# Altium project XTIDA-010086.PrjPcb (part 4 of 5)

## Sheet XTIDA-010086_Bias Power Supply.SchDoc: Control card
size 431 x 279 mm; Date: Not shown in title block; ApprovedBy: Not shown in title block; CheckedBy: Not shown in title block; Author: Not shown in title block; CompanyName: Not shown in title block; DrawnBy: Jeff Xie; Engineer: Not shown in title block; Organization: Not shown in title block; Address1: Not shown in title block; Address2: Not shown in title block; Address3: Not shown in title block; Address4: Not shown in title block; DocumentNumber: 2; Revision: Use project parameter SCH_Rev; SheetNumber: 7; SheetTotal: 8; PageSetup: Record=PageOptions¦CenterHorizontal=True¦CenterVertical=True¦PrintScale=1.00¦XCorrection=1.00¦YCorrection=1.00¦PrintKind=0¦BorderSize=5000000¦LeftOffset=0¦BottomOffset=0¦Orientation=2¦PaperLength=1000¦PaperWidth=1000¦Scale=100¦PaperSource=15¦PrintQuality=600¦MediaType=1¦DitherType=10¦PaperKind=Letter¦PrintScaleMode=1
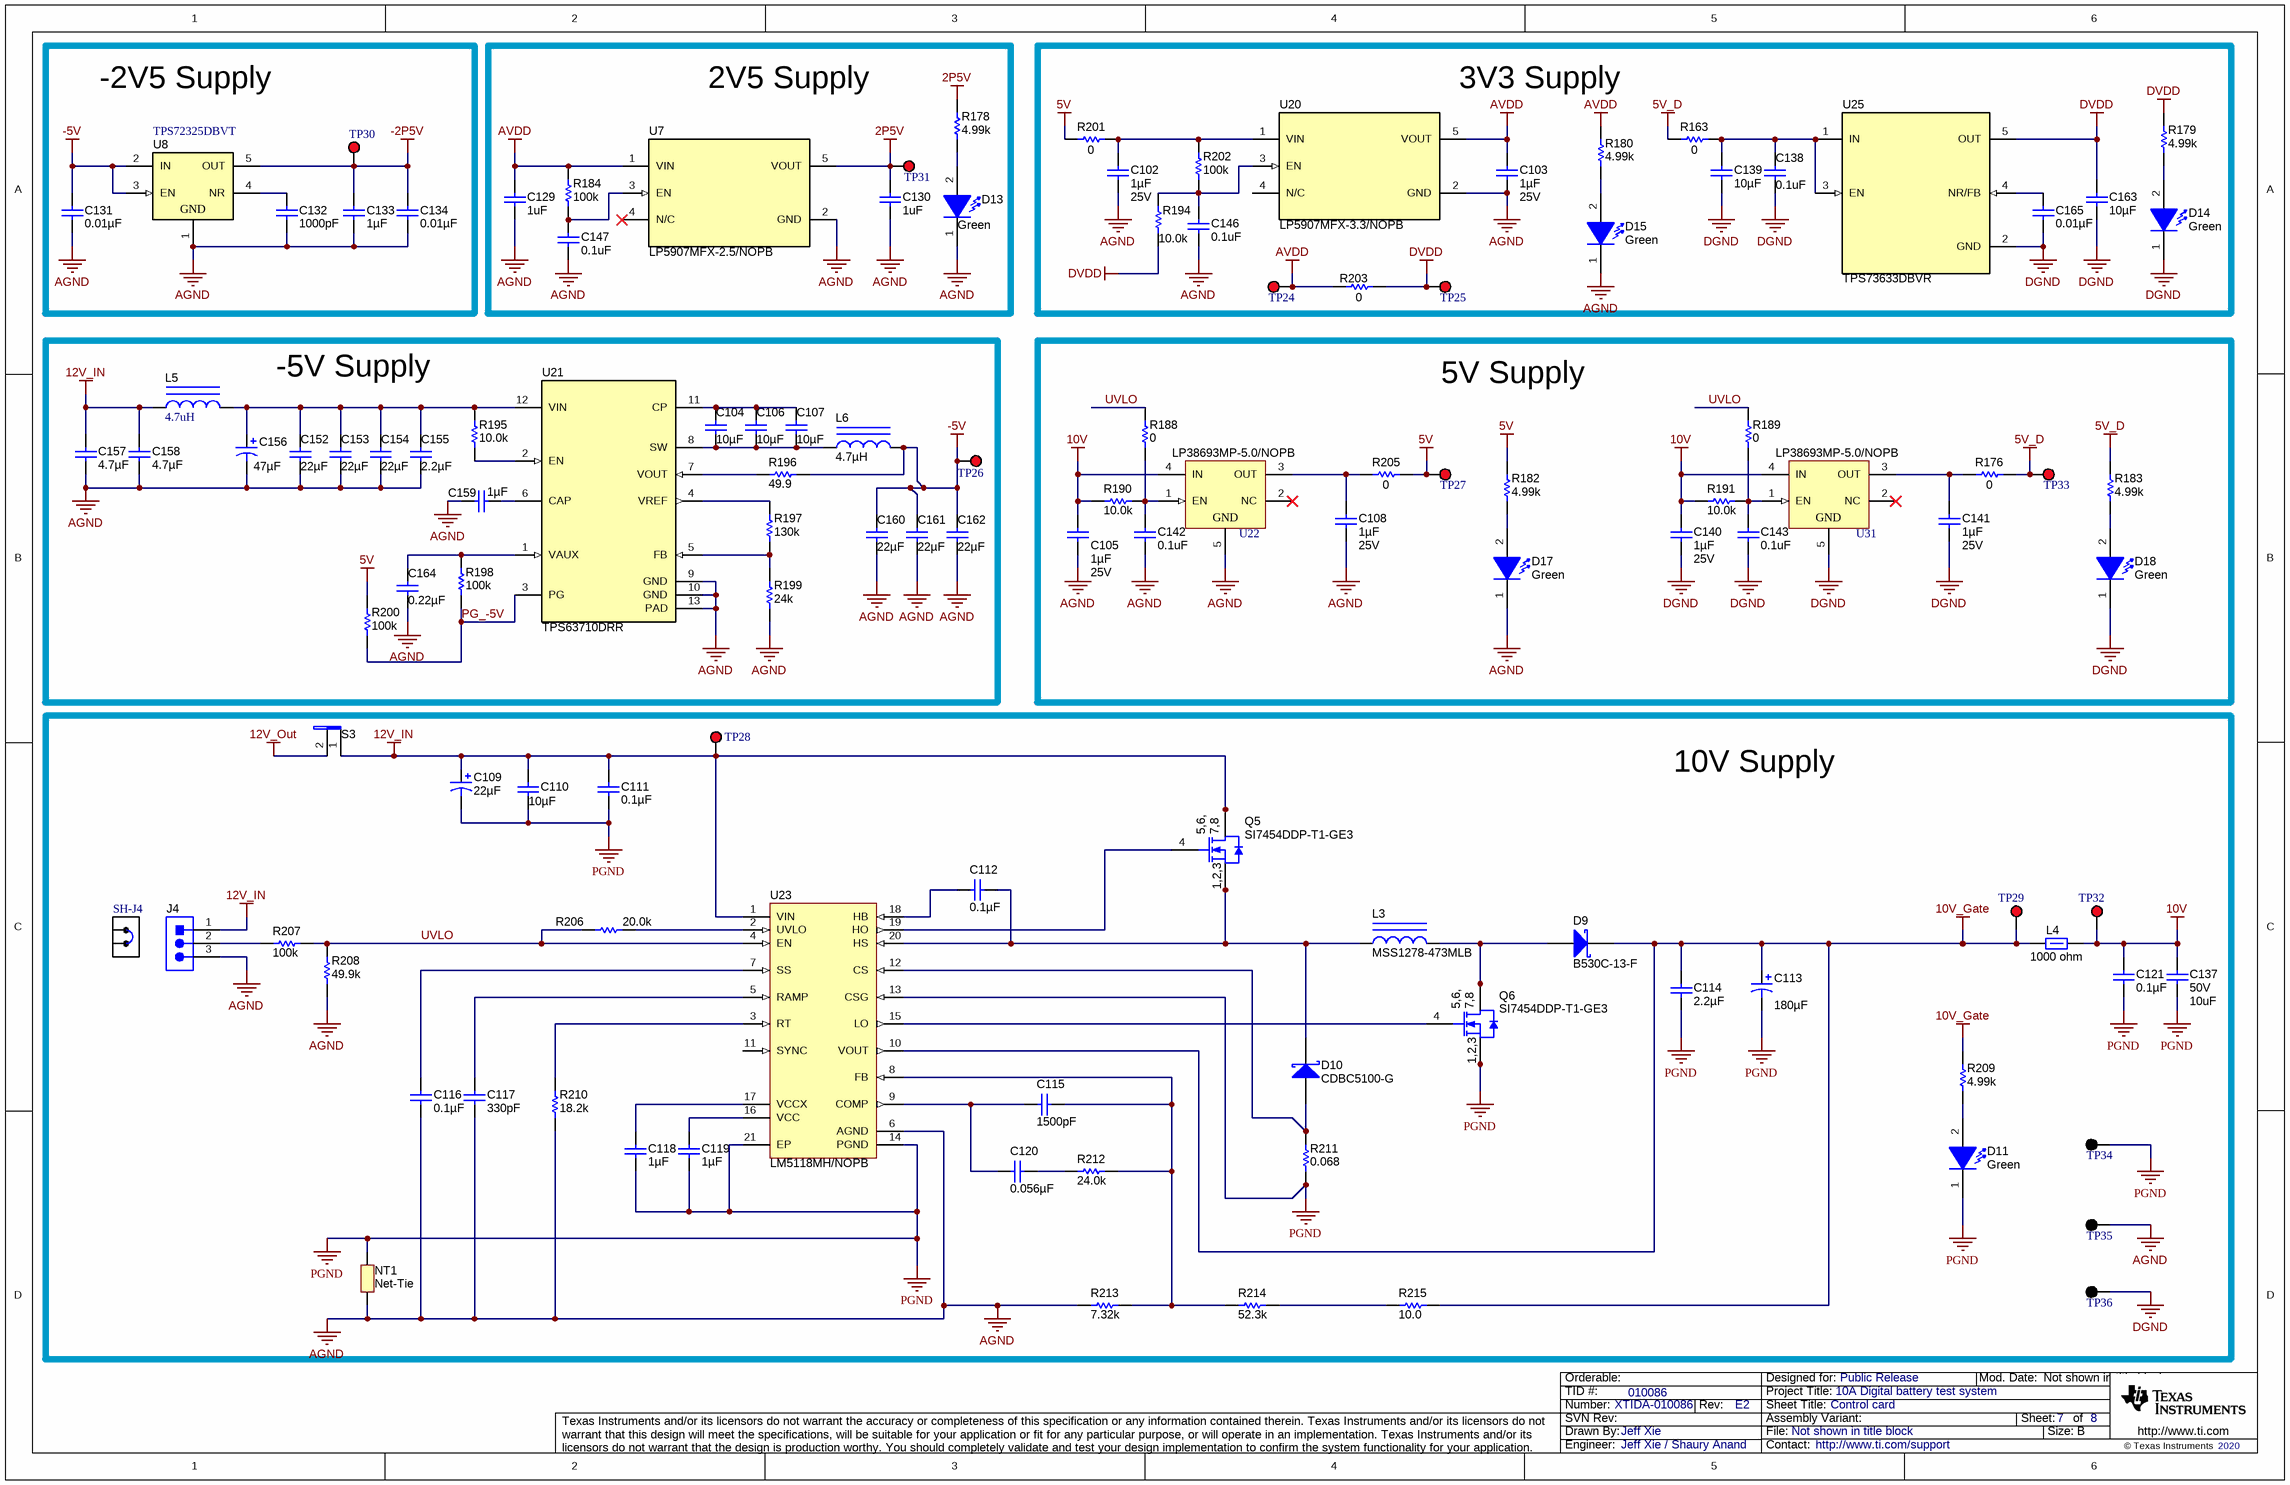
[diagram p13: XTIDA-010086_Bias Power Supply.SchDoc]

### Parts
C102  Cap_F: 1µF  VDC_V: 25V  [0603]  (hidden comment: C0603C105K3RACTU)
C103  Cap_F: 1µF  VDC_V: 25V  [0603]  (hidden comment: C0603C105K3RACTU)
C104  ValueDisplayed: 10µF  [0805_HV1]  (hidden comment: EMK212BB7106MG-T)
C105  Cap_F: 1µF  VDC_V: 25V  [0603]  (hidden comment: C0603C105K3RACTU)
C106  ValueDisplayed: 10µF  [0805_HV1]  (hidden comment: EMK212BB7106MG-T)
C107  ValueDisplayed: 10µF  [0805_HV1]  (hidden comment: EMK212BB7106MG-T)
C108  Cap_F: 1µF  VDC_V: 25V  [0603]  (hidden comment: C0603C105K3RACTU)
C109  ValueDisplayed: 22µF  [CAPSMT_62_JA0]  (hidden comment: EMVH101ADA220MJA0G)
C110  ValueDisplayed: 10µF  [2220_250]  (hidden comment: C5750X7S2A106M230KB)
C111  ValueDisplayed: 0.1µF  [0805_HV]  (hidden comment: C2012X7R2A104K125AA)
C112  ValueDisplayed: 0.1µF  [0603L]  (hidden comment: GRM188R72A104KA35D)
C113  ValueDisplayed: 180µF  [CAPSMT_62_HC0]  (hidden comment: APXA160ARA181MHC0G)
C114  ValueDisplayed: 2.2µF  [0805_HV]  (hidden comment: C2012X7R1C225K125AB)
C115  ValueDisplayed: 1500pF  [0603L]  (hidden comment: GRM1885C2A152JA01D)
C116  ValueDisplayed: 0.1µF  [0603L]  (hidden comment: GRM188R72A104KA35D)
C117  ValueDisplayed: 330pF  [0603L]  (hidden comment: C1608C0G2A331J080AA)
C118  ValueDisplayed: 1µF  [0603L]  (hidden comment: GRM188R71E105KA12D)
C119  ValueDisplayed: 1µF  [0603L]  (hidden comment: GRM188R71E105KA12D)
C120  ValueDisplayed: 0.056µF  [0603L]  (hidden comment: GRM188R71H563KA93D)
C121  ValueDisplayed: 0.1µF  [0805_HV]  (hidden comment: C2012X7R2A104K125AA)
C129  ValueDisplayed: 1uF  [0805_HV]  (hidden comment: Capacitor)
C130  ValueDisplayed: 1uF  [0805_HV]  (hidden comment: Capacitor)
C131  ValueDisplayed: 0.01µF  [0603]  (hidden comment: 06031C103KAT2A)
C132  ValueDisplayed: 1000pF  [0603]  (hidden comment: 06031C102JAT2A)
C133  ValueDisplayed: 1µF  [0603]  (hidden comment: GRM188R71E105KA12D)
C134  ValueDisplayed: 0.01µF  [0603]  (hidden comment: 06031C103KAT2A)
C137  VDC_V: 50V  ValueDisplayed: 10uF  [1210_280]  (hidden comment: C3225X7R1H106M250AC)
C138  ValueDisplayed: 0.1uF  [0603]  (hidden comment: Capacitor)
C139  ValueDisplayed: 10µF  [0603]  (hidden comment: GRM188R61E106MA73D)
C140  Cap_F: 1µF  VDC_V: 25V  [0603]  (hidden comment: C0603C105K3RACTU)
C141  Cap_F: 1µF  VDC_V: 25V  [0603]  (hidden comment: C0603C105K3RACTU)
C142  ValueDisplayed: 0.1uF  [0603]  (hidden comment: Capacitor)
C143  ValueDisplayed: 0.1uF  [0603]  (hidden comment: Capacitor)
C146  ValueDisplayed: 0.1uF  [0603]  (hidden comment: Capacitor)
C147  ValueDisplayed: 0.1uF  [0603]  (hidden comment: Capacitor)
C152  ValueDisplayed: 22µF  [1206_190]  (hidden comment: EMK316BB7226ML-T)
C153  ValueDisplayed: 22µF  [1206_190]  (hidden comment: EMK316BB7226ML-T)
C154  ValueDisplayed: 22µF  [1206_190]  (hidden comment: EMK316BB7226ML-T)
C155  ValueDisplayed: 2.2µF  [0603_HV]  (hidden comment: EMK107BB7225KA-T)
C156  ValueDisplayed: 47µF  [F95_B]  (hidden comment: F951C476MBAAQ2)
C157  ValueDisplayed: 4.7µF  [1206]  (hidden comment: GRM319R61E475KA12D)
C158  ValueDisplayed: 4.7µF  [1206]  (hidden comment: GRM319R61E475KA12D)
C159  ValueDisplayed: 1µF  [0402]  (hidden comment: C1005X5R1C105K050BC)
C160  ValueDisplayed: 22µF  [0805_HV1]  (hidden comment: C2012X7S1A226M125AC)
C161  ValueDisplayed: 22µF  [0805_HV1]  (hidden comment: C2012X7S1A226M125AC)
C162  ValueDisplayed: 22µF  [0805_HV1]  (hidden comment: C2012X7S1A226M125AC)
C163  ValueDisplayed: 10µF  [0603]  (hidden comment: GRM188R61E106MA73D)
C164  ValueDisplayed: 0.22µF  [0402]  (hidden comment: GRM155R71C224KA12D)
C165  ValueDisplayed: 0.01µF  [0603]  (hidden comment: 06031C103KAT2A)
D9  B530C-13-F  [SMC]
D10  CDBC5100-G  [SMC]
D11  value Green  [WL-SMCW_GREEN]  (hidden comment: 150060VS75000)
D13  value Green  [WL-SMCW_GREEN]  (hidden comment: 150060VS75000)
D14  value Green  [WL-SMCW_GREEN]  (hidden comment: 150060VS75000)
D15  value Green  [WL-SMCW_GREEN]  (hidden comment: 150060VS75000)
D17  value Green  [WL-SMCW_GREEN]  (hidden comment: 150060VS75000)
D18  value Green  [WL-SMCW_GREEN]  (hidden comment: 150060VS75000)
J4  0022284033  [Molex_0022284033]  (value not drawn)
L3  MSS1278-473MLB  [mss1278]
L4  value 1000 ohm  [1806_HighSpeed]  (hidden comment: BLM41PG102SN1L)
L5  ValueDisplayed: 4.7uH  [MAKK2016]  (hidden comment: MAKK2016T4R7M)
L6  ValueDisplayed: 4.7µH  [XFL4020]  (hidden comment: XFL4020-472MEB)
NT1  Net-Tie  [Net-Tie_10mil]  (net tie, no BOM)
Q5  SI7454DDP-T1-GE3  [PowerPAK_SO-8]
Q6  SI7454DDP-T1-GE3  [PowerPAK_SO-8]
R163  ValueDisplayed: 0  [0603]  (hidden comment: Resistor)
R176  ValueDisplayed: 0  [0603]  (hidden comment: Resistor)
R178  ValueDisplayed: 4.99k  [0603L]  (hidden comment: CRCW06034K99FKEA)
R179  ValueDisplayed: 4.99k  [0603L]  (hidden comment: CRCW06034K99FKEA)
R180  ValueDisplayed: 4.99k  [0603L]  (hidden comment: CRCW06034K99FKEA)
R182  ValueDisplayed: 4.99k  [0603L]  (hidden comment: CRCW06034K99FKEA)
R183  ValueDisplayed: 4.99k  [0603L]  (hidden comment: CRCW06034K99FKEA)
R184  ValueDisplayed: 100k  [0603]  (hidden comment: CRCW0603100KFKEA)
R188  ValueDisplayed: 0  [0402]  (hidden comment: CRCW04020000Z0ED)
R189  ValueDisplayed: 0  [0402]  (hidden comment: CRCW04020000Z0ED)
R190  ValueDisplayed: 10.0k  [0603]  (hidden comment: RC0603FR-0710KL)
R191  ValueDisplayed: 10.0k  [0603]  (hidden comment: RC0603FR-0710KL)
R194  ValueDisplayed: 10.0k  [0603]  (hidden comment: RC0603FR-0710KL)
R195  ValueDisplayed: 10.0k  [0603]  (hidden comment: RC0603FR-0710KL)
R196  ValueDisplayed: 49.9  [0402]  (hidden comment: CRCW040249R9FKED)
R197  ValueDisplayed: 130k  [0402]  (hidden comment: CRCW0402130KFKED)
R198  ValueDisplayed: 100k  [0402]  (hidden comment: CRCW0402100KDHEDP)
R199  ValueDisplayed: 24k  [0402]  (hidden comment: CRCW040224K0JNED)
R200  ValueDisplayed: 100k  [0402]  (hidden comment: CRCW0402100KDHEDP)
R201  ValueDisplayed: 0  [0603]  (hidden comment: Resistor)
R202  ValueDisplayed: 100k  [0603]  (hidden comment: CRCW0603100KFKEA)
R203  ValueDisplayed: 0  [0603]  (hidden comment: Resistor)
R205  ValueDisplayed: 0  [0603]  (hidden comment: Resistor)
R206  ValueDisplayed: 20.0k  [0603L]  (hidden comment: CRCW060320K0FKEA)
R207  ValueDisplayed: 100k  [0603]  (hidden comment: RC0603FR-07100KL)
R208  ValueDisplayed: 49.9k  [0603]  (hidden comment: CRCW060349K9FKEA)
R209  ValueDisplayed: 4.99k  [0603L]  (hidden comment: CRCW06034K99FKEA)
R210  ValueDisplayed: 18.2k  [0603L]  (hidden comment: CRCW060318K2FKEA)
R211  ValueDisplayed: 0.068  [0612]  (hidden comment: PRL1632-R068-F-T1)
R212  ValueDisplayed: 24.0k  [0603L]  (hidden comment: RC0603FR-0724KL)
R213  ValueDisplayed: 7.32k  [0603]  (hidden comment: RC0603FR-077K32L)
R214  ValueDisplayed: 52.3k  [0603]  (hidden comment: RC0603FR-0752K3L)
R215  ValueDisplayed: 10.0  [0603L]  (hidden comment: CRCW060310R0FKEA)
S3  L101011MS02Q  [SW_ L101011MS02Q]  (value not drawn)
SH-J4  60900213421  [Wurth_60900213421]  (value not drawn)
TP24  5000  [Keystone5000]  (value not drawn)
TP25  5000  [Keystone5000]  (value not drawn)
TP26  5000  [Keystone5000]  (value not drawn)
TP27  5000  [Keystone5000]  (value not drawn)
TP28  5000  [Keystone5000]  (value not drawn)
TP29  5000  [Keystone5000]  (value not drawn)
TP30  5000  [Keystone5000]  (value not drawn)
TP31  5000  [Keystone5000]  (value not drawn)
TP32  5000  [Keystone5000]  (value not drawn)
TP33  5000  [Keystone5000]  (value not drawn)
TP34  5001  [Keystone5001]  (value not drawn)
TP35  5001  [Keystone5001]  (value not drawn)
TP36  5001  [Keystone5001]  (value not drawn)
U7  LP5907MFX-2.5/NOPB  [DBV0005A_L]
U8  TPS72325DBVT  [DBV0005A_N]
U20  LP5907MFX-3.3/NOPB  [DBV0005A_N]
U21  TPS63710DRR  [DRR0012C]
U22  LP38693MP-5.0/NOPB  [NDC0005A_N]
U23  LM5118MH/NOPB  [MXA20A_N]
U25  TPS73633DBVR  [DBV0005A_N]
U31  LP38693MP-5.0/NOPB  [NDC0005A_N]

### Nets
2P5V: C130.1 R178.1 TP31.1 U7.5(VOUT)
5V: R182.1 R200.2 R201.1 R205.2 TP27.1
5V_D: R163.1 R176.2 R183.1 TP33.1
10V: C105.1 C121.1 C137.1 C140.1 L4.2 R190.2 R191.2 TP32.1 U22.4(IN) U31.4(IN)
10V_Gate: C113.1(+) C114.1 D9.1(K) L4.1 R209.1 R215.2 TP29.1 U23.10(VOUT)
12V_IN: C109.1(+) C110.1 C111.1 C157.1 C158.1 J4.1 L5.1 Q5.5(D) Q5.6(D) Q5.7(D) Q5.8(D) Q5.9(D) S3.1 TP28.1 U23.1(VIN)
12V_Out: S3.2
-2P5V: C133.1 C134.1 TP30.1 U8.5(OUT)
-5V: C131.1 C160.1 C161.1 C162.1 L6.2 R196.1 TP26.1 U8.2(IN) U8.3(EN)
AGND: C102.2 C103.2 C105.2 C108.2 C116.2 C117.2 C129.2 C130.2 C131.2 C132.2 C133.2 C134.2 C142.2 C146.2 C147.2 C152.2 C153.2 C154.2 C155.2 C156.2(-) C157.2 C158.2 C159.1 C160.2 C161.2 C162.2 C164.2 D13.1(K) D15.1(K) D17.1(K) J4.3 NT1.1 R199.1 R208.1 R210.1 R213.1 TP35.1 U7.2(GND) U8.1(GND) U20.2(GND) U21.9(GND) U21.10(GND) U21.13(PAD) U22.5(GND) U23.6(AGND)
AVDD: C103.1 C129.1 R180.1 R184.2 R203.1 TP24.1 U7.1(VIN) U20.5(VOUT)
DGND: C138.2 C139.2 C140.2 C141.2 C143.2 C163.2 C165.2 D14.1(K) D18.1(K) TP36.1 U25.2(GND) U31.5(GND)
DVDD: C163.1 R179.1 R194.1 R203.2 TP25.1 U25.5(OUT)
PGND: C109.2(-) C110.2 C111.2 C113.2(-) C114.2 C118.2 C119.2 C121.2 C137.2 D11.1(K) NT1.2 Q6.1(S) Q6.2(S) Q6.3(S) R211.1 TP34.1 U23.13(CSG) U23.14(PGND) U23.21(EP)
PG_-5V: R198.1 R200.1 U21.3(PG)
UVLO: R188.1 R189.1 R206.1 R207.1 R208.2 U23.4(EN)
NetC102_1: C102.1 R201.2 R202.2 U20.1(VIN)
NetC104_1: C104.1 C106.1 C107.1 U21.11(CP)
NetC104_2: C104.2 C106.2 C107.2 L6.1 U21.8(SW)
NetC108_1: C108.1 R205.1 U22.3(OUT)
NetC112_1: C112.1 D10.1(K) L3.1 Q5.1(S) Q5.2(S) Q5.3(S) U23.20(HS)
NetC112_2: C112.2 U23.18(HB)
NetC115_1: C115.1 C120.1 U23.9(COMP)
NetC115_2: C115.2 R212.1 R213.2 R214.1 U23.8(FB)
NetC116_1: C116.1 U23.7(SS)
NetC117_1: C117.1 U23.5(RAMP)
NetC118_1: C118.1 U23.17(VCCX)
NetC119_1: C119.1 U23.16(VCC)
NetC120_2: C120.2 R212.2
NetC132_1: C132.1 U8.4(NR)
NetC138_1: C138.1 C139.1 R163.2 U25.1(IN) U25.3(EN)
NetC141_1: C141.1 R176.1 U31.3(OUT)
NetC142_1: C142.1 R188.2 R190.1 U22.1(EN)
NetC143_1: C143.1 R189.2 R191.1 U31.1(EN)
NetC146_1: C146.1 R194.2 R202.1 U20.3(EN)
NetC147_1: C147.1 R184.1 U7.3(EN)
NetC152_1: C152.1 C153.1 C154.1 C155.1 C156.1(+) L5.2 R195.1 U21.12(VIN)
NetC159_2: C159.2 U21.6(CAP)
NetC164_1: C164.1 R198.2 U21.1(VAUX)
NetC165_1: C165.1 U25.4(NR/FB)
NetD9_2: D9.2(A) L3.2 Q6.5(D) Q6.6(D) Q6.7(D) Q6.8(D) Q6.9(D)
NetD10_2: D10.2(A) R211.2 U23.12(CS)
NetD11_2: D11.2(A) R209.2
NetD13_2: D13.2(A) R178.2
NetD14_2: D14.2(A) R179.2
NetD15_2: D15.2(A) R180.2
NetD17_2: D17.2(A) R182.2
NetD18_2: D18.2(A) R183.2
NetJ4_2: J4.2 R207.2
NetQ5_4: Q5.4(G) U23.19(HO)
NetQ6_4: Q6.4(G) U23.15(LO)
NetR195_2: R195.2 U21.2(EN)
NetR196_2: R196.2 U21.7(VOUT)
NetR197_1: R197.1 R199.2 U21.5(FB)
NetR197_2: R197.2 U21.4(VREF)
NetR206_2: R206.2 U23.2(UVLO)
NetR210_2: R210.2 U23.3(RT)
NetR214_2: R214.2 R215.1

Not connected (* = marked no-connect by the designer): U7 4(N/C)*; U20 4(N/C); U22 2(NC)*; U23 11(SYNC); U31 2(NC)*

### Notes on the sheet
- -2V5 Supply
- 2V5 Supply
- 3V3 Supply
- -5V Supply
- (near R189) 5V Supply
- 10V Supply

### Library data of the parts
C102 C103 C105 C108 C140 C141 = CMP-0006867-1: CAP, CERM, 1 uF, 25 V, +/- 10%, X7R, 0603; Manufacturer: Kemet; TaMin_C: -55°C; Polarized: N; SizeAreaWB_mm2: 4.68; Value1: Unknown; U/M: EA; Value: 1uF; TaMax_C: 125°C; SizeZ_mm: 1; SizeX_mm: 1.6; SizeY_mm: 0.8; SizeArea_mm2: 1.28; AEC Category: Q200
C104 C106 C107 = EMK212BB7106MG-T: CAP, CERM, 10 µF, 16 V, +/- 20%, X7R, 0805; Manufacturer: Taiyo Yuden; Polarized: N; CompType: Capacitor; Value: 10uF; U/M: EA; Cap_F: 0.00001; Tolerance_%: 20; Value1: Unknown; VDC_V: 16; Value2: 16V; TaMin_C: -55; TaMax_C: 125; Cap_Case: 0805; AEC Category: Q200
C109 = EMVH101ADA220MJA0G: CAP, AL, 22 µF, 100 V, +/- 20%, 0.55 ohm, SMD; Manufacturer: Chemi-Con; Polarized: Y; CompType: Capacitor; Value: 22uF; U/M: EA; Cap_F: 0.000022; Tolerance_%: 20; VDC_V: 100; Value2: 100V; ESR_ohm: 0.55; IRMS_A: 0.115; TaMin_C: -40; TaMax_C: 125; Cap_Case: JA0
C110 = C5750X7S2A106M230KB: CAP, CERM, 10 µF, 100 V, +/- 20%, X7S,; Manufacturer: TDK; Polarized: N; CompType: Capacitor; Value: 10uF; U/M: EA; Cap_F: 0.00001; Tolerance_%: 20; ESR_ohm: 0.005; Value1: 0.005 ohm; VDC_V: 100; Value2: 100V; IRMS_A: 6.45; TaMin_C: -55; TaMax_C: 125; Cap_Case: 2220; SizeArea_mm2: 28.5; SizeAreaWB_mm2: 53.9; SizeX_mm: 5.7; SizeY_mm: 5; SizeZ_mm: 2.5; AEC Category: Q200
C111 = C2012X7R2A104K125AA: CAP, CERM, 0.1 µF, 100 V, +/- 10%, X7R, 0805; Manufacturer: TDK; Polarized: N; CompType: Capacitor; Value: 0.1uF; U/M: EA; Cap_F: 0.0000001; Tolerance_%: 10; ESR_ohm: 0.0158; Value1: 0.0158 ohm; VDC_V: 100; Value2: 100V; TaMin_C: -55; TaMax_C: 125; Cap_Case: 0805; AEC Category: Q200
C112 C116 = GRM188R72A104KA35D: CAP, CERM, 0.1 µF, 100 V, +/- 10%, X7R, 0603; Manufacturer: MuRata; Polarized: N; CompType: Capacitor; Value: 0.1uF; U/M: EA; Cap_F: 0.0000001; Tolerance_%: 10; Value1: Unknown; VDC_V: 100; Value2: 100V; TaMin_C: -55; TaMax_C: 125; Cap_Case: 0603; AEC Category: Q200
C113 = APXA160ARA181MHC0G: CAP, Aluminum Polymer, 180 µF, 16 V, +/- 20%, 0.016 ohm, HC0 SMD; Manufacturer: Chemi-Con; Polarized: Y; CompType: Capacitor; Value: 180uF; U/M: EA; Cap_F: 0.00018; Tolerance_%: 20; VDC_V: 16; Value2: 16V; ESR_ohm: 0.016; IRMS_A: 4.36; TaMin_C: -55; TaMax_C: 105; SizeAreaWB_mm2: 110.25; SizeArea_mm2: 72.25; SizeX_mm: 8.5; SizeZ_mm: 12.3; AEC Category: Q200; AEC Qualified: N
C114 = C2012X7R1C225K125AB: CAP, CERM, 2.2 µF, 16 V, +/- 10%, X7R, 0805; Manufacturer: TDK; Polarized: N; CompType: Capacitor; Value: 2.2uF; U/M: EA; Cap_F: 0.0000022; Tolerance_%: 10; ESR_ohm: 0.0049; Value1: 0.0049 ohm; VDC_V: 16; Value2: 16V; TaMin_C: -55; TaMax_C: 125; Cap_Case: 0805; AEC Category: Q200
C115 = GRM1885C2A152JA01D: CAP, CERM, 1500 pF, 100 V, +/- 5%, C0G/NP0, 0603; Manufacturer: MuRata; Polarized: N; CompType: Capacitor; Value: 1500pF; U/M: EA; Cap_F: 0.0000000015; Tolerance_%: 5; Value1: Unknown; VDC_V: 100; Value2: 100V; TaMin_C: -55; TaMax_C: 125; Cap_Case: 0603
C117 = C1608C0G2A331J080AA: CAP, CERM, 330 pF, 100 V, +/- 5%, C0G/NP0, 0603; Manufacturer: TDK; Polarized: N; CompType: Capacitor; Value: 330pF; U/M: EA; Cap_F: 0.00000000033; Tolerance_%: 5; ESR_ohm: 0.1269; Value1: 0.1269 ohm; VDC_V: 100; Value2: 100V; TaMin_C: -55; TaMax_C: 125; Cap_Case: 0603; AEC Category: Q200
C118 C119 = GRM188R71E105KA12D: CAP, CERM, 1 µF, 25 V, +/- 10%, X7R, 0603; Manufacturer: MuRata; Polarized: N; CompType: Capacitor; Value: 1uF; U/M: EA; Cap_F: 0.000001; Tolerance_%: 10; Value1: Unknown; VDC_V: 25; Value2: 25V; TaMin_C: -55; TaMax_C: 125; Cap_Case: 0603
C120 = GRM188R71H563KA93D: CAP, CERM, 0.056 µF, 50 V, +/- 10%, X7R, 0603; Manufacturer: MuRata; Polarized: N; CompType: Capacitor; Value: 0.056uF; U/M: EA; Cap_F: 0.000000056; Tolerance_%: 10; Value1: Unknown; VDC_V: 50; Value2: 50V; TaMin_C: -55; TaMax_C: 125; Cap_Case: 0603
C121 = C2012X7R2A104K125AA: CAP, CERM, 0.1 µF, 100 V, +/- 10%, X7R, 0805; Manufacturer: TDK; Polarized: N; CompType: Capacitor; Value: 0.1uF; U/M: EA; Cap_F: 0.0000001; Tolerance_%: 10; ESR_ohm: 0.020726; Value1: 0.020726 ohm; VDC_V: 100; Value2: 100V; IRMS_A: 1.456; TaMin_C: -55; TaMax_C: 125; Cap_Case: 0805; SizeArea_mm2: 2.5; SizeAreaWB_mm2: 6.75; SizeX_mm: 2; SizeY_mm: 1.25; SizeZ_mm: 1.45; AEC Category: Q200
C129 C130 = CMP-0007891-2: CAP, CERM, 1 uF, 100 V, +/- 10%, X7S, 0805; PartNumber: C2012X7S2A105K125AB; Manufacturer: TDK; Polarized: N; Value: 1uF; U/M: EA; Cap_F: 1µF; ESR_ohm: 8.255m; Value1: 0.008255 ohm; VDC_V: 100V; IRMS_A: 2.27442A; TaMin_C: -55°C; TaMax_C: 125°C; Cap_Case: 0805; AEC Category: Q200; SizeArea_mm2: 2.5; SizeAreaWB_mm2: 6.75; SizeX_mm: 2; SizeY_mm: 1.25; SizeZ_mm: 1.45
C131 C134 C165 = 06031C103KAT2A: CAP, CERM, 0.01 µF, 100 V, +/- 10%, X7R, 0603; Manufacturer: AVX; Polarized: N; CompType: Capacitor; Value: 0.01uF; U/M: EA; Cap_F: 0.00000001; Tolerance_%: 10; ESR_ohm: 0.098; Value1: 0.098 ohm; VDC_V: 100; Value2: 100V; TaMin_C: -55; TaMax_C: 125; AEC Category: Q200
C132 = 06031C102JAT2A: CAP, CERM, 1000 pF, 100 V, +/- 5%, X7R, 0603; Manufacturer: AVX; Polarized: N; CompType: Capacitor; Value: 1000pF; U/M: EA; Cap_F: 0.000000001; Tolerance_%: 5; ESR_ohm: 0.276; Value1: 0.276 ohm; VDC_V: 100; Value2: 100V; TaMin_C: -55; TaMax_C: 125; AEC Category: Q200
C133 = GRM188R71E105KA12D: CAP, CERM, 1 µF, 25 V, +/- 10%, X7R, 0603; Manufacturer: MuRata; Polarized: N; CompType: Capacitor; Value: 1uF; U/M: EA; Cap_F: 0.000001; Tolerance_%: 10; Value1: Unknown; VDC_V: 25; Value2: 25V; TaMin_C: -55; TaMax_C: 125; AEC Category: Q200
C137 = CMP-0009120-1: CAP, CERM, 10 uF, 50 V, +/- 20%, X7R, 1210; Manufacturer: TDK; TaMin_C: -55°C; Polarized: N; SizeAreaWB_mm2: 14.7; Value1: Unknown; U/M: EA; Value: 10uF; TaMax_C: 125°C; SizeZ_mm: 2.8; SizeX_mm: 3.2; SizeY_mm: 2.5; Cap_Case: 1210; SizeArea_mm2: 8; Cap_F: 10µF; AEC Category: Q200
C138 C142 C143 C146 C147 = CMP-0006752-5: CAP, CERM, 0.1 uF, 25 V, +/- 5%, X7R, 0603; PartNumber: 06033C104JAT2A; Manufacturer: AVX; Polarized: N; Value: 0.1uF; U/M: EA; Cap_F: 100nF; ESR_ohm: 0.05; Value1: 0.05 ohm; VDC_V: 25V; TaMin_C: -55°C; TaMax_C: 125°C; AEC Category: Q200; SizeArea_mm2: 1.28; SizeAreaWB_mm2: 4.68; SizeX_mm: 1.6; SizeY_mm: 0.8; SizeZ_mm: 1
C139 C163 = GRM188R61E106MA73D: CAP, CERM, 10 µF, 25 V,+/- 20%, X5R, 0603; Manufacturer: MuRata; Polarized: N; CompType: Capacitor; Value: 10uF; U/M: EA; Cap_F: 0.00001; Tolerance_%: 20; VDC_V: 25; Value2: 25V; TaMin_C: -55; TaMax_C: 85; SizeArea_mm2: 1.28; SizeAreaWB_mm2: 4.68; SizeX_mm: 1.6; SizeY_mm: 0.8; SizeZ_mm: 1; AEC Category: Q200; Green_Lifecycle: Active; Green_REACh: Passed
C152-C154 = EMK316BB7226ML-T: CAP, CERM, 22 µF, 16 V, +/- 20%, X7R, 1206_190; Manufacturer: Taiyo Yuden; Polarized: N; CompType: Capacitor; Value: 22uF; U/M: EA; Cap_F: 0.000022; Tolerance_%: 20; Value1: Unknown; VDC_V: 16; Value2: 16V; TaMin_C: -55; TaMax_C: 125; Cap_Case: 1206; SizeArea_mm2: 5.12; SizeAreaWB_mm2: 10.92; SizeX_mm: 3.2; SizeY_mm: 1.6; SizeZ_mm: 1.9; AEC Category: Q200
C155 = EMK107BB7225KA-T: CAP, CERM, 2.2 µF, 16 V, +/- 10%, X7R, 0603; Manufacturer: Taiyo Yuden; Polarized: N; CompType: Capacitor; Value: 2.2uF; U/M: EA; Cap_F: 0.0000022; Tolerance_%: 10; Value1: Unknown; VDC_V: 16; Value2: 16V; TaMin_C: -55; TaMax_C: 125; Cap_Case: 0603; AEC Category: Q200
C156 = F951C476MBAAQ2: CAP, TA, 47 µF, 16 V, +/- 20%, 0.6 ohm, SMD; Manufacturer: AVX; Polarized: Y; CompType: Capacitor; Value: 47uF; U/M: EA; Cap_F: 0.000047; Tolerance_%: 20; Value1: 0.6 ohm; VDC_V: 16; Value2: 16V; ESR_ohm: 0.6; TaMin_C: -55; TaMax_C: 125; SizeAreaWB_mm2: 17.1; SizeArea_mm2: 9.8; SizeX_mm: 3.5; SizeY_mm: 2.8; SizeZ_mm: 2; AEC Category: Q200
C157 C158 = GRM319R61E475KA12D: CAP, CERM, 4.7 µF, 25 V,+/- 10%, X5R, 1206; Manufacturer: MuRata; Polarized: N; CompType: Capacitor; Value: 4.7uF; U/M: EA; Cap_F: 0.0000047; Tolerance_%: 10; ESR_ohm: 0.006; Value1: 0.006 ohm; VDC_V: 25; Value2: 25V; TaMin_C: -55; TaMax_C: 85; SizeArea_mm2: 5.12; SizeAreaWB_mm2: 10.92; SizeX_mm: 3.2; SizeY_mm: 1.6; SizeZ_mm: 1.35; AEC Category: Q200
C159 = C1005X5R1C105K050BC: CAP, CERM, 1 µF, 16 V,+/- 10%, X5R, 0402; Manufacturer: TDK; Polarized: N; CompType: Capacitor; Value: 1uF; U/M: EA; Cap_F: 0.000001; Tolerance_%: 10; VDC_V: 16; Value2: 16V; TaMin_C: -55; TaMax_C: 85; SizeArea_mm2: 0.5; SizeAreaWB_mm2: 3; SizeX_mm: 1; SizeZ_mm: 0.6; AEC Category: Q200; Green_Lifecycle: EOL; Green_REACh: Passed
C160-C162 = C2012X7S1A226M125AC: CAP, CERM, 22 µF, 10 V, +/- 20%, X7S, 0805; Manufacturer: TDK; Polarized: N; CompType: Capacitor; Value: 22uF; U/M: EA; Cap_F: 0.000022; Tolerance_%: 20; Value1: Unknown; VDC_V: 10; Value2: 10V; TaMin_C: -55; TaMax_C: 125; Cap_Case: 0805; AEC Category: Q200
C164 = GRM155R71C224KA12D: CAP, CERM, 0.22 µF, 16 V,+/- 10%, X7R, 0402; Manufacturer: MuRata; Polarized: N; CompType: Capacitor; Value: 0.22uF; U/M: EA; Cap_F: 0.00000022; Tolerance_%: 10; VDC_V: 16; Value2: 16V; TaMin_C: -55; TaMax_C: 125; SizeArea_mm2: 0.5; SizeAreaWB_mm2: 3; SizeX_mm: 1; SizeZ_mm: 0.6; AEC Category: Q200; Green_Lifecycle: Active; Green_REACh: Passed
D9 = B530C-13-F: Diode, Schottky, 30 V, 5 A, SMC; Manufacturer: Diodes Inc.; U/M: EA; Vf_V: 0.55; Value: 30V; Value1: 5A; Value2: 0.55V; Io_A: 5; Vr_V: 30; TJmax_C: 125; RJC_CperW: 10
D10 = CDBC5100-G: Diode, Schottky, 100 V, 5 A, SMC; Manufacturer: Comchip Technology; U/M: EA; Vf_V: 0.85; Value: 100V; Value1: 5A; Value2: 0.85V; Io_A: 5; Vr_V: 100; TJmax_C: 125
D11 D13-D15 D17 D18 = 150060VS75000: LED, Green, SMD; Manufacturer: Wurth Elektronik; Type: AlInGaP; Vf_V: 2; Value2: 2V; Io_A: 0.02; Value1: W; U/M: EA
J4 = 0022284033: Header, 2.54mm, 3x1, Tin, TH; Manufacturer: Molex; SymbolCreator: a0799628; Pitch_mm: 2.54; Gender: Male; Shrouded: N; Row_Count: 1; Current_A: 4; Voltage_V: 250; Cert_UL: Y
L3 = MSS1278-473MLB: Inductor, Shielded Drum Core, Ferrite, 47 µH, 2.9 A, 0.07 ohm, SMD; Manufacturer: Coilcraft; Value: 47uH; Ind_H: 47.0E-6; ValueDisplayed: 47µH; Imax_A: 2.9; Irms: 2.9A @ 40C rise; Isat: 5.32A @ 30% inductance drop; DCR_ohm: 0.07; Value2: 2.9A
L4 = CMP-0003369-1: Ferrite Bead, 1000 ohm @ 100 MHz, 1.5 A, 1806; Manufacturer: MuRata; ZTyp@100MHz_Ohm: 1k; SizeAreaWB_mm2: 14.3; DCR_ohm: 0.09; Value1: 0.09 ohm; Imax_A: 1.5A; SizeZ_mm: 1.85; SizeX_mm: 4.5; SizeY_mm: 1.6; SizeArea_mm2: 7.2
L5 = CMP-0059761-1: Inductor, Wirewound, 4.7 uH, 0.95 A, 0.38 ohm, SMD; Manufacturer: Taiyo Yuden; Isat: 1A @ 30% inductance drop; Irms: 0.95A @ 40C rise; Green_Lifecycle: Active; SizeAreaWB_mm2: 7.8; DCR_ohm: 0.38; Green_REACh: Passed; Value: 4.7uH; Imax_A: 950mA; SizeZ_mm: 1; SizeX_mm: 2; SizeY_mm: 1.6; Value2: 0.95A; SizeArea_mm2: 3.2; Ind_H: 4.7µH; AEC Category: Q200
L6 = XFL4020-472MEB: Inductor, Shielded, Composite, 4.7 µH, 2.7 A, 0.05 ohm, SMD; Manufacturer: Coilcraft; Value: 4.7uH; Ind_H: 4.7E-6; Imax_A: 2.7; Irms: 5A @ 40C rise; Isat: 2.7A @ 30% inductance drop; DCR_ohm: 0.05; Value2: 2.7A; AEC Category: Q200
NT1 = Net-Tie: Single point connection between nets.; SymbolCreator: codlsc
Q5 Q6 = SI7454DDP-T1-GE3: MOSFET, N-CH, 100 V, 21 A, PowerPAK SO-8; Manufacturer: Vishay-Siliconix; Alternate Manufacturer: None; U/M: EA; ChType: N; Value: 100V; VdsMax_V: 100; Value1: 0.047 ohm; Rdson45_ohm: 0.047; Value2: 12.8 nC; QgTyp_nC: 12.8; Vgs_V: 20; IdsMax_A: 21; SizeAreaWB_mm2: 55.131; SizeArea_mm2: 29.351; SizeX_mm: 5.99; SizeY_mm: 4.9; SizeZ_mm: 1.12; AEC Category: Q101
R163 R176 R201 R203 R205 = CMP-0025874-3: RES, 0, 5%, 0.1 W, 0603; PartNumber: ERJ-3GEY0R00V; Manufacturer: Panasonic; Value: 0; Value_Code: 0000; Power_W: 100mW; Value2: 0.1W; VDC_V: 50V; TempCo: 600 ppm/C; EIA_Code: E24; U/M: EA; AEC Category: Q200; SizeArea_mm2: 1.28; SizeX_mm: 1.6; SizeY_mm: 0.8; SizeZ_mm: 1
R178-R180 R182 R183 R209 = CRCW06034K99FKEA: RES, 4.99 k, 1%, 0.1 W, 0603; Manufacturer: Vishay-Dale; CompType: Resistor; Value: 4.99k; Res_ohm: 4990; Value_Code: 4k99; Tolerance_%: 1; Power_W: 0.1; Value2: 0.1W; VDC_V: 75; TempCo: 100 ppm/C; EIA_Code: E96; U/M: EA
R184 R202 = CMP-0021990-1: RES, 100 k, 1%, 0.1 W, 0603; Manufacturer: Vishay-Dale; Power_W: 100mW; TempCo: 100 ppm/C; U/M: EA; Value: 100k; EIA_Code: E96; SizeX_mm: 1.6; SizeY_mm: 0.8; SizeZ_mm: 1; Value2: 0.1W; SizeArea_mm2: 1.28; VDC_V: 75V; AEC Category: Q200
R188 R189 = CRCW04020000Z0ED: RES, 0, 5%, 0.063 W, 0402; Manufacturer: Vishay-Dale; CompType: Resistor; Value: 0; Value_Code: 0000; Tolerance_%: 5; Power_W: 0.063; Value2: 0.063W; VDC_V: 50; TempCo: 200 ppm/C; SizeArea_mm2: 0.5; SizeX_mm: 1; SizeZ_mm: 0.6; EIA_Code: E24; U/M: EA; AEC Category: Q200; Green_Lifecycle: Active; Green_REACh: Passed
R190 R191 R194 R195 = CMP-0022746-5: RES, 10.0 k, 1%, 0.1 W, 0603; Manufacturer: Yageo; Power_W: 100mW; TempCo: 100 ppm/C; Value_Code: 10k0; Value: 10.0k; EIA_Code: E96; Res_ohm: 10k; SizeX_mm: 1.6; SizeY_mm: 0.8; SizeZ_mm: 1; Value2: 0.1W; SizeArea_mm2: 1.28; AEC Qualified: N; VDC_V: 75V; AEC Category: Q200; SizeAreaWB_mm2: 4.68
R196 = CRCW040249R9FKED: RES, 49.9, 1%, 0.063 W, 0402; Manufacturer: Vishay-Dale; CompType: Resistor; Value: 49.9; Value_Code: 49R9; Tolerance_%: 1; Power_W: 0.063; Value2: 0.063W; VDC_V: 50; TempCo: 100 ppm/C; SizeArea_mm2: 0.5; SizeZ_mm: 0.6; EIA_Code: E96; U/M: EA; AEC Category: Q200; Green_Lifecycle: Active; Green_REACh: Passed
R197 = CRCW0402130KFKED: RES, 130 k, 1%, 0.063 W, 0402; Manufacturer: Vishay-Dale; CompType: Resistor; Value: 130k; Res_ohm: 130000; Tolerance_%: 1; Power_W: 0.063; Value2: 0.063W; VDC_V: 50; TempCo: 100 ppm/C; SizeArea_mm2: 0.5; SizeZ_mm: 0.6; EIA_Code: E96; U/M: EA; AEC Category: Q200; Green_Lifecycle: Active; Green_REACh: Passed
R198 R200 = CRCW0402100KDHEDP: RES, 100 k, 0.5%, 0.063 W, 0402; Manufacturer: Vishay-Dale; CompType: Resistor; Value: 100k; Res_ohm: 100000; Tolerance_%: 0.5; Power_W: 0.063; Value2: 0.063W; VDC_V: 50; TempCo: 50 ppm/C; SizeX_mm: 1; SizeZ_mm: 0.6; EIA_Code: E192; U/M: EA; AEC Category: Q200; Green_Lifecycle: Active; Green_REACh: Passed
R199 = CRCW040224K0JNED: RES, 24 k, 5%, 0.063 W, 0402; Manufacturer: Vishay-Dale; CompType: Resistor; Value: 24k; Res_ohm: 24000; Value_Code: 24k0; Tolerance_%: 5; Power_W: 0.063; Value2: 0.063W; VDC_V: 50; TempCo: 200 ppm/C; SizeArea_mm2: 0.5; SizeX_mm: 1; SizeZ_mm: 0.6; EIA_Code: E24; U/M: EA; AEC Category: Q200; Green_Lifecycle: Active; Green_REACh: Passed
R206 = CRCW060320K0FKEA: RES, 20.0 k, 1%, 0.1 W, 0603; Manufacturer: Vishay-Dale; CompType: Resistor; Value: 20.0k; Res_ohm: 20000; Value_Code: 20k0; Tolerance_%: 1; Power_W: 0.1; Value2: 0.1W; VDC_V: 75; TempCo: 100 ppm/C; EIA_Code: E96; U/M: EA; AEC Category: Q200
R207 = RC0603FR-07100KL: RES, 100 k, 1%, 0.1 W, 0603; Manufacturer: Yageo America; CompType: Resistor; Value: 100k; Res_ohm: 100000; Tolerance_%: 1; Power_W: 0.1; Value2: 0.1W; VDC_V: 150; TempCo: 200 ppm/C; SizeArea_mm2: 1.28; SizeX_mm: 1.6; SizeY_mm: 0.8; EIA_Code: E96; U/M: EA; AEC Category: Q200; Green_Lifecycle: Active; Green_REACh: Passed
R208 = CRCW060349K9FKEA: RES, 49.9 k, 1%, 0.1 W, 0603; Manufacturer: Vishay-Dale; CompType: Resistor; Value: 49.9k; Res_ohm: 49900; Value_Code: 49k9; Tolerance_%: 1; Power_W: 0.1; Value2: 0.1W; VDC_V: 75; TempCo: 100 ppm/C; SizeArea_mm2: 1.28; SizeX_mm: 1.6; SizeY_mm: 0.8; EIA_Code: E96; U/M: EA; AEC Category: Q200; Green_Lifecycle: Active; Green_REACh: Passed
R210 = CRCW060318K2FKEA: RES, 18.2 k, 1%, 0.1 W, 0603; Manufacturer: Vishay-Dale; CompType: Resistor; Value: 18.2k; Res_ohm: 18200; Value_Code: 18k2; Tolerance_%: 1; Power_W: 0.1; Value2: 0.1W; VDC_V: 75; TempCo: 100 ppm/C; EIA_Code: E96; U/M: EA
R211 = PRL1632-R068-F-T1: RES, 0.068, 1%, 1 W, 0612; Manufacturer: Susumu Co Ltd; CompType: Resistor; Value: 0.068; Value_Code: R068; Tolerance_%: 1; Value2: 1W; TempCo: 50 ppm/C; U/M: EA
R212 = RC0603FR-0724KL: RES, 24.0 k, 1%, 0.1 W, 0603; Manufacturer: Yageo America; CompType: Resistor; Value: 24.0k; Res_ohm: 24000; Value_Code: 24k0; Tolerance_%: 1; Power_W: 0.1; Value2: 0.1W; VDC_V: 150; TempCo: 200 ppm/C; U/M: EA
R213 = CMP-0023278-3: RES, 7.32 k, 1%, 0.1 W, 0603; Manufacturer: Yageo America; Power_W: 100mW; TempCo: 200 ppm/C; Value_Code: 7k32; U/M: EA; Value: 7.32k; EIA_Code: E96; SizeX_mm: 1.6; SizeY_mm: 0.8; SizeZ_mm: 1; Value2: 0.1W; SizeArea_mm2: 1.28; CompType: Resistor; VDC_V: 150V; AEC Category: Q200
R214 = CMP-0023172-3: RES, 52.3 k, 1%, 0.1 W, 0603; Manufacturer: Yageo America; Power_W: 100mW; TempCo: 200 ppm/C; Value_Code: 52k3; U/M: EA; Value: 52.3k; EIA_Code: E96; SizeX_mm: 1.6; SizeY_mm: 0.8; SizeZ_mm: 1; Value2: 0.1W; SizeArea_mm2: 1.28; CompType: Resistor; VDC_V: 150V; AEC Category: Q200
R215 = CRCW060310R0FKEA: RES, 10.0, 1%, 0.1 W, 0603; Manufacturer: Vishay-Dale; CompType: Resistor; Value: 10.0; Res_ohm: 10; Value_Code: 10R0; Tolerance_%: 1; Power_W: 0.1; Value2: 0.1W; VDC_V: 75; TempCo: 100 ppm/C; EIA_Code: E96; U/M: EA
S3 = L101011MS02Q: SWITCH SLIDE SPST 4A PCB, TH; Manufacturer: C&K Components; Symbol Creator: a0411947; VDC_V: 125; SwitchFunction: Off-On; PositionCount: 1; CurrentRating_mA: 4000
SH-J4 = 60900213421: Shunt, 2.54mm, Gold, Black; Manufacturer: Wurth Elektronik; Green_Lifecycle: Active; Green_REACh: Passed
TP24-TP33 = 5000: Test Point, Miniature, Red, TH; Manufacturer: Keystone; CompType: Test Point Loop; ContactFinish: Silver; Green_Lifecycle: Active; Green_REACh: Passed
TP34-TP36 = 5001: Test Point, Miniature, Black, TH; Manufacturer: Keystone; CompType: Test Point Loop; ContactFinish: Silver; Green_Lifecycle: Active; Green_REACh: Passed
U7 = CMP-0076238-1: 250-mA Ultra-Low-Noise, Low-IQ LDO, DBV0005A (SOT-23-5); Manufacturer: Texas Instruments; SizeAreaWB_mm2: 14.82; SizeArea_mm2: 8.12; SizeZ_mm: 1.45; SizeY_mm: 2.9; U/M: EA; CompType: IC; SizeX_mm: 2.8
U8 = TPS72325DBVT: Single Output High PSRR LDO, 200 mA, Fixed -2.5 V Output, -10 to -2.7 V Input, 5-pin SOT-23 (DBV), -40 to 125 degC, Green (RoHS & no Sb/Br); Manufacturer: Texas Instruments; Alternate PartNumber: Equivalent; Accuracy(%): 2; Iout(Max)(A): 0.2; Iq(Typ)(mA): 0.13; SubFamily: Single Channel LDO; Vdo(Typ)(mV): 280
U20 = CMP-0066020-1: 250-mA Ultra-Low-Noise, Low-IQ LDO, DBV0005A (SOT-23-5); Alternate Manufacturer: Texas Instruments; Green_Lifecycle: Active; SizeAreaWB_mm2: 14.82; Green_REACh: Passed; U/M: EA; SizeZ_mm: 1.45; SizeX_mm: 2.8; SizeY_mm: 2.9; SizeArea_mm2: 8.12; CompType: IC
U21 = TPS63710DRR: Synchronous Inverting Buck Converter, DRR0012C; Manufacturer: Texas Instruments; SymbolCreator: Altium; SizeArea_mm2: 9; SizeAreaWB_mm2: 16; SizeX_mm: 3; SizeZ_mm: 0.8; CompType: IC; U/M: EA
U22 U31 = CMP-0070852-1: 500mA Low Dropout CMOS Linear Regulators Stable with Ceramic Output Capacitors, 5-pin SOT-223, Pb-Free, 1000 Reel; Manufacturer: Texas Instruments; CompType: LDO IC; PowerWise: Y; PackageTopMarking: XYTT*LJZB
U23 = LM5118MH/NOPB: Wide Voltage Range Buck-Boost Controller, 20-pin TSSOP-EP, Pb-Free; Manufacturer: Texas Instruments; PackageTopMarking: NSUZXYTT*LM5118*MH; PowerWise: Y; CompType: Switcher
U25 = CMP-0036866-2: Single Output Low Noise LDO, 400 mA, Fixed 3.3 V Output, 1.7 to 5.5 V Input, with Reverse Current Protection, 5-pin SOT-23 (DBV), -40 to 85 degC, Green (RoHS & no Sb/Br); Manufacturer: Texas Instruments; Alternate PartNumber: TPS73633DBVT; Vout Adj(Min)(V): 3.3; Rating: Catalog; Accuracy(%): 1; Iq(Typ)(mA): 0.3; Vin(Max)(V): 5.5; SubFamily: Single Channel LDO; Vdo(Typ)(mV): 75; Vin(Min)(V): 1.7; Iout(Max)(A): 0.4; AEC Category: Q200; AEC Qualified: N; CompType: IC; Green_Lifecycle: Active; Green_REACh: Passed; SizeAreaWB_mm2: 14.82; SizeArea_mm2: 8.12; SizeX_mm: 2.8; SizeY_mm: 2.9; SizeZ_mm: 1.45

## Sheet XTIDA-010086_Control Card_28379.SchDoc: Control card
size 558 x 431 mm; Date: Not shown in title block; ApprovedBy: Not shown in title block; CheckedBy: Not shown in title block; Author: Not shown in title block; CompanyName: Not shown in title block; DrawnBy: Jeff Xie; Engineer: Not shown in title block; Organization: Not shown in title block; Address1: Not shown in title block; Address2: Not shown in title block; Address3: Not shown in title block; Address4: Not shown in title block; DocumentNumber: 2; Revision: Use project parameter SCH_Rev; SheetNumber: 6; SheetTotal: 8; PageSetup: Record=PageOptions¦CenterHorizontal=True¦CenterVertical=True¦PrintScale=1.00¦XCorrection=1.00¦YCorrection=1.00¦PrintKind=0¦BorderSize=5000000¦LeftOffset=0¦BottomOffset=0¦Orientation=2¦PaperLength=1000¦PaperWidth=1000¦Scale=100¦PaperSource=15¦PrintQuality=600¦MediaType=1¦DitherType=10¦PaperKind=Letter¦PrintScaleMode=1
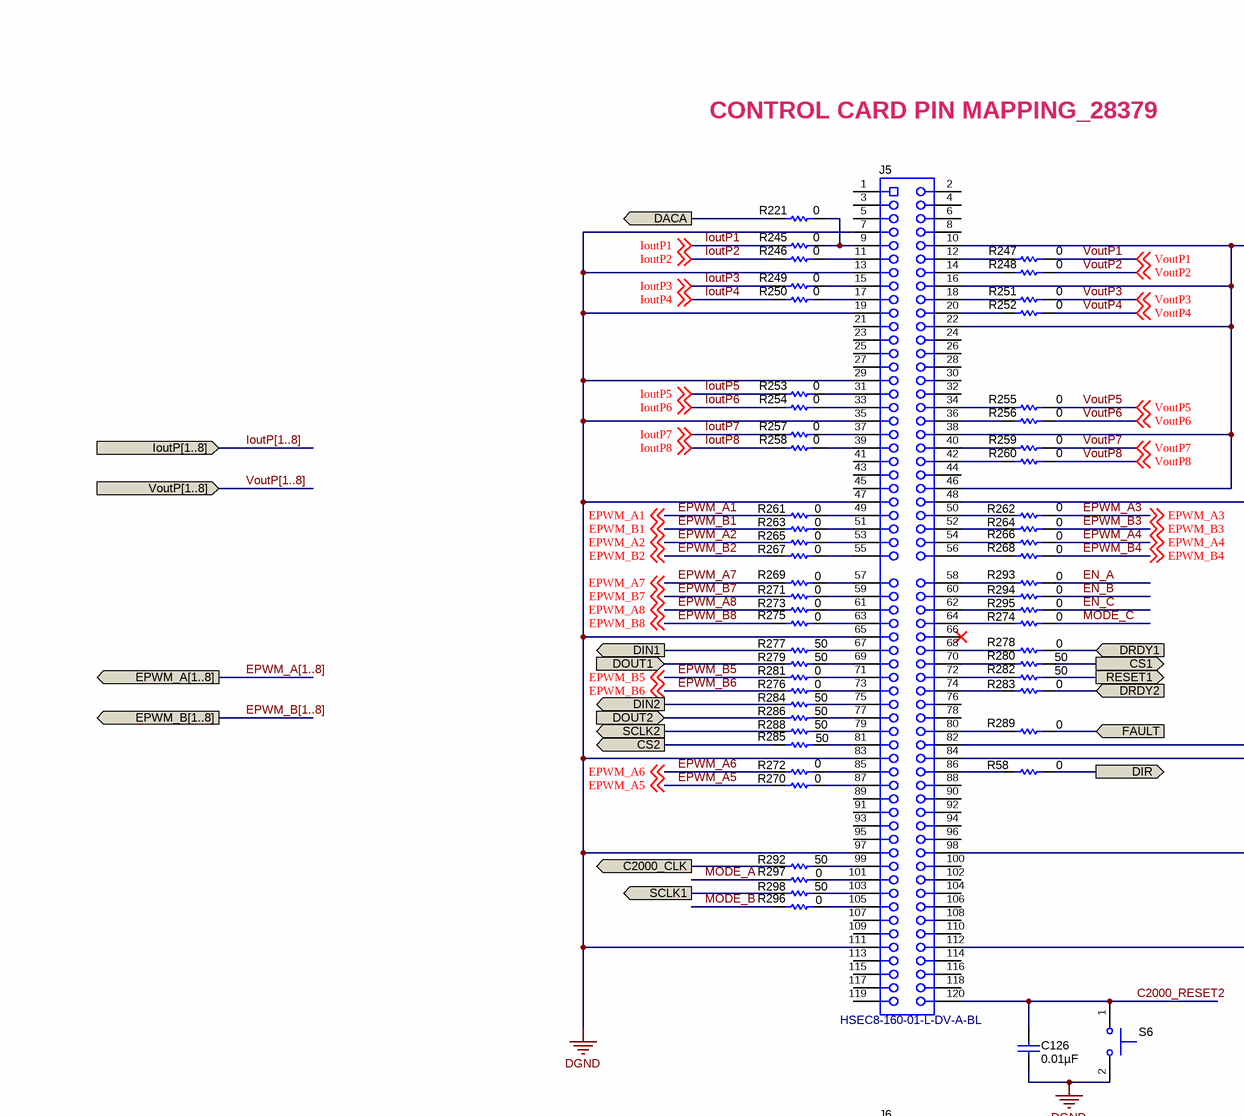
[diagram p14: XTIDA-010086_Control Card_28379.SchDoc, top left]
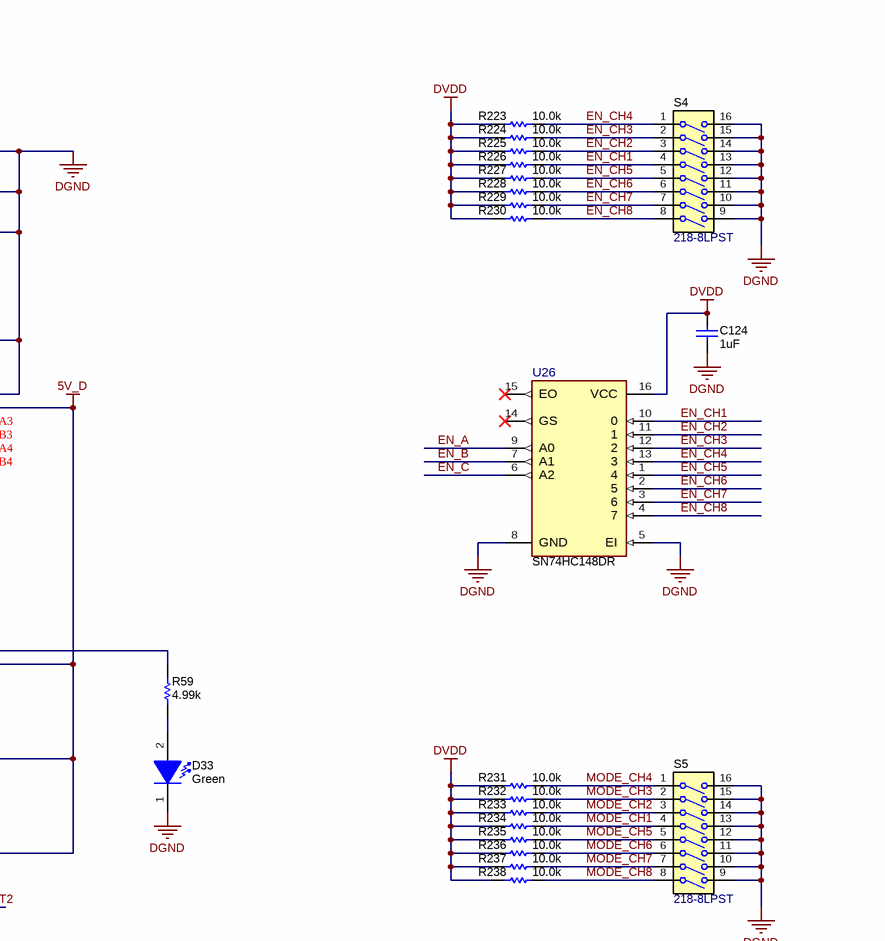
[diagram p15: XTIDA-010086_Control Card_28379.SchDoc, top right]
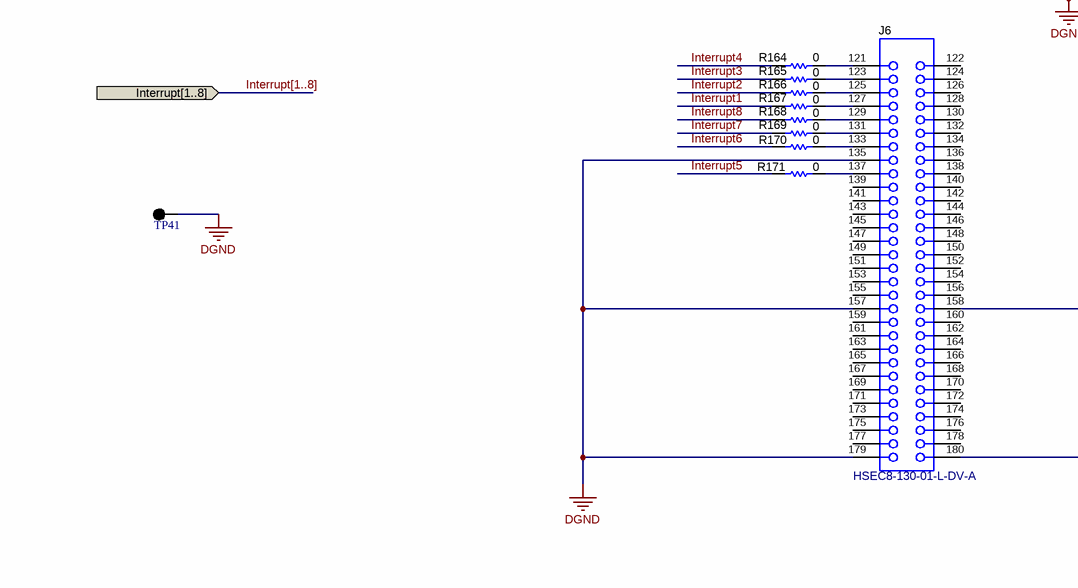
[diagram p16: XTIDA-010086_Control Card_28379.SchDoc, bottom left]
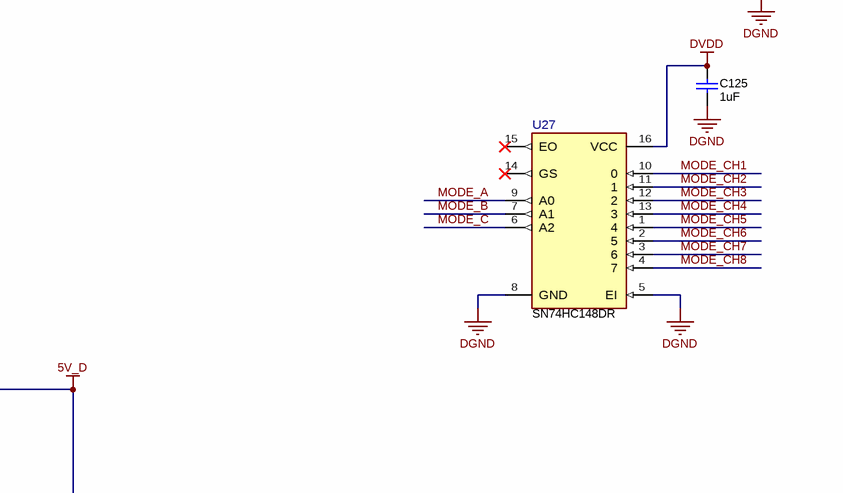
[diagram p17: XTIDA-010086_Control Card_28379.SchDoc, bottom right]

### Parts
C124  ValueDisplayed: 1uF  [0603]  (hidden comment: Capacitor)
C125  ValueDisplayed: 1uF  [0603]  (hidden comment: Capacitor)
C126  ValueDisplayed: 0.01µF  [0603]  (hidden comment: C0603C103J3GECAUTO)
D33  value Green  [WL-SMCW_GREEN]  (hidden comment: 150060VS75000)
J5  HSEC8-160-01-L-DV-A-BL  [controlCARD-120HSEC]
J6  HSEC8-130-01-L-DV-A  [controlCARD-180HSEC-60pinAddon]
R58  ValueDisplayed: 0  [0402]  (hidden comment: CRCW04020000Z0ED)
R59  ValueDisplayed: 4.99k  [0603L]  (hidden comment: CRCW06034K99FKEA)
R164  ValueDisplayed: 0  [0402]  (hidden comment: CRCW04020000Z0ED)
R165  ValueDisplayed: 0  [0402]  (hidden comment: CRCW04020000Z0ED)
R166  ValueDisplayed: 0  [0402]  (hidden comment: CRCW04020000Z0ED)
R167  ValueDisplayed: 0  [0402]  (hidden comment: CRCW04020000Z0ED)
R168  ValueDisplayed: 0  [0402]  (hidden comment: CRCW04020000Z0ED)
R169  ValueDisplayed: 0  [0402]  (hidden comment: CRCW04020000Z0ED)
R170  ValueDisplayed: 0  [0402]  (hidden comment: CRCW04020000Z0ED)
R171  ValueDisplayed: 0  [0402]  (hidden comment: CRCW04020000Z0ED)
R221  ValueDisplayed: 0  [0402]  (hidden comment: CRCW04020000Z0ED)
R223  ValueDisplayed: 10.0k  [0402]  (hidden comment: CRCW040210K0FKED)
R224  ValueDisplayed: 10.0k  [0402]  (hidden comment: CRCW040210K0FKED)
R225  ValueDisplayed: 10.0k  [0402]  (hidden comment: CRCW040210K0FKED)
R226  ValueDisplayed: 10.0k  [0402]  (hidden comment: CRCW040210K0FKED)
R227  ValueDisplayed: 10.0k  [0402]  (hidden comment: CRCW040210K0FKED)
R228  ValueDisplayed: 10.0k  [0402]  (hidden comment: CRCW040210K0FKED)
R229  ValueDisplayed: 10.0k  [0402]  (hidden comment: CRCW040210K0FKED)
R230  ValueDisplayed: 10.0k  [0402]  (hidden comment: CRCW040210K0FKED)
R231  ValueDisplayed: 10.0k  [0402]  (hidden comment: CRCW040210K0FKED)
R232  ValueDisplayed: 10.0k  [0402]  (hidden comment: CRCW040210K0FKED)
R233  ValueDisplayed: 10.0k  [0402]  (hidden comment: CRCW040210K0FKED)
R234  ValueDisplayed: 10.0k  [0402]  (hidden comment: CRCW040210K0FKED)
R235  ValueDisplayed: 10.0k  [0402]  (hidden comment: CRCW040210K0FKED)
R236  ValueDisplayed: 10.0k  [0402]  (hidden comment: CRCW040210K0FKED)
R237  ValueDisplayed: 10.0k  [0402]  (hidden comment: CRCW040210K0FKED)
R238  ValueDisplayed: 10.0k  [0402]  (hidden comment: CRCW040210K0FKED)
R245  ValueDisplayed: 0  [0402]  (hidden comment: CRCW04020000Z0ED)
R246  ValueDisplayed: 0  [0402]  (hidden comment: CRCW04020000Z0ED)
R247  ValueDisplayed: 0  [0402]  (hidden comment: CRCW04020000Z0ED)
R248  ValueDisplayed: 0  [0402]  (hidden comment: CRCW04020000Z0ED)
R249  ValueDisplayed: 0  [0402]  (hidden comment: CRCW04020000Z0ED)
R250  ValueDisplayed: 0  [0402]  (hidden comment: CRCW04020000Z0ED)
R251  ValueDisplayed: 0  [0402]  (hidden comment: CRCW04020000Z0ED)
R252  ValueDisplayed: 0  [0402]  (hidden comment: CRCW04020000Z0ED)
R253  ValueDisplayed: 0  [0402]  (hidden comment: CRCW04020000Z0ED)
R254  ValueDisplayed: 0  [0402]  (hidden comment: CRCW04020000Z0ED)
R255  ValueDisplayed: 0  [0402]  (hidden comment: CRCW04020000Z0ED)
R256  ValueDisplayed: 0  [0402]  (hidden comment: CRCW04020000Z0ED)
R257  ValueDisplayed: 0  [0402]  (hidden comment: CRCW04020000Z0ED)
R258  ValueDisplayed: 0  [0402]  (hidden comment: CRCW04020000Z0ED)
R259  ValueDisplayed: 0  [0402]  (hidden comment: CRCW04020000Z0ED)
R260  ValueDisplayed: 0  [0402]  (hidden comment: CRCW04020000Z0ED)
R261  ValueDisplayed: 0  [0402]  (hidden comment: CRCW04020000Z0ED)
R262  ValueDisplayed: 0  [0402]  (hidden comment: CRCW04020000Z0ED)
R263  ValueDisplayed: 0  [0402]  (hidden comment: CRCW04020000Z0ED)
R264  ValueDisplayed: 0  [0402]  (hidden comment: CRCW04020000Z0ED)
R265  ValueDisplayed: 0  [0402]  (hidden comment: CRCW04020000Z0ED)
R266  ValueDisplayed: 0  [0402]  (hidden comment: CRCW04020000Z0ED)
R267  ValueDisplayed: 0  [0402]  (hidden comment: CRCW04020000Z0ED)
R268  ValueDisplayed: 0  [0402]  (hidden comment: CRCW04020000Z0ED)
R269  ValueDisplayed: 0  [0402]  (hidden comment: CRCW04020000Z0ED)
R270  ValueDisplayed: 0  [0402]  (hidden comment: CRCW04020000Z0ED)
R271  ValueDisplayed: 0  [0402]  (hidden comment: CRCW04020000Z0ED)
R272  ValueDisplayed: 0  [0402]  (hidden comment: CRCW04020000Z0ED)
R273  ValueDisplayed: 0  [0402]  (hidden comment: CRCW04020000Z0ED)
R274  ValueDisplayed: 0  [0402]  (hidden comment: CRCW04020000Z0ED)
R275  ValueDisplayed: 0  [0402]  (hidden comment: CRCW04020000Z0ED)
R276  ValueDisplayed: 0  [0402]  (hidden comment: CRCW04020000Z0ED)
R277  ValueDisplayed: 50  [0402]  (hidden comment: FC0402E50R0BST1)
R278  ValueDisplayed: 0  [0402]  (hidden comment: CRCW04020000Z0ED)
R279  ValueDisplayed: 50  [0402]  (hidden comment: FC0402E50R0BST1)
R280  ValueDisplayed: 50  [0402]  (hidden comment: FC0402E50R0BST1)
R281  ValueDisplayed: 0  [0402]  (hidden comment: CRCW04020000Z0ED)
R282  ValueDisplayed: 50  [0402]  (hidden comment: FC0402E50R0BST1)
R283  ValueDisplayed: 0  [0402]  (hidden comment: CRCW04020000Z0ED)
R284  ValueDisplayed: 50  [0402]  (hidden comment: FC0402E50R0BST1)
R285  ValueDisplayed: 50  [0402]  (hidden comment: FC0402E50R0BST1)
R286  ValueDisplayed: 50  [0402]  (hidden comment: FC0402E50R0BST1)
R288  ValueDisplayed: 50  [0402]  (hidden comment: FC0402E50R0BST1)
R289  ValueDisplayed: 0  [0402]  (hidden comment: CRCW04020000Z0ED)
R292  ValueDisplayed: 50  [0402]  (hidden comment: FC0402E50R0BST1)
R293  ValueDisplayed: 0  [0402]  (hidden comment: CRCW04020000Z0ED)
R294  ValueDisplayed: 0  [0402]  (hidden comment: CRCW04020000Z0ED)
R295  ValueDisplayed: 0  [0402]  (hidden comment: CRCW04020000Z0ED)
R296  ValueDisplayed: 0  [0402]  (hidden comment: CRCW04020000Z0ED)
R297  ValueDisplayed: 0  [0402]  (hidden comment: CRCW04020000Z0ED)
R298  ValueDisplayed: 50  [0402]  (hidden comment: FC0402E50R0BST1)
S4  218-8LPST  [SW_218-8LP]
S5  218-8LPST  [SW_218-8LP]
S6  Switch_PushButton  [SW_TL1015AF160QG]  (value not drawn)
TP41  5001  [Keystone5001]  (value not drawn)
U26  SN74HC148DR  [D0016A-MFG]
U27  SN74HC148DR  [D0016A-MFG]

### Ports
C2000_CLK (out), CS1 (out), CS2 (out), DACA (out), DIN1 (out), DIN2 (out), DIR (out), DOUT1 (in), DOUT2 (in), DRDY1 (in), DRDY2 (in), EPWM_A[1..8] (out), EPWM_B[1..8] (out), FAULT (in), Interrupt[1..8] (in), IoutP[1..8] (in), RESET1 (out), SCLK1 (out), SCLK2 (out), VoutP[1..8] (in)

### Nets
5V_D: J5.48 J5.84 J5.98 J5.112 J6.158 J6.180
DGND: C124.2 C125.2 C126.2 D33.1(K) J5.7 J5.10 J5.13 J5.16 J5.19 J5.22 J5.29 J5.35 J5.38 J5.46 J5.47 J5.65 J5.83 J5.97 J5.111 J6.135 J6.157 J6.179 S4.9(8A) S4.10(7A) S4.11(6A) S4.12(5A) S4.13(4A) S4.14(3A) S4.15(2A) S4.16(1A) S5.9(8A) S5.10(7A) S5.11(6A) S5.12(5A) S5.13(4A) S5.14(3A) S5.15(2A) S5.16(1A) S6.2 TP41.1 U26.5(EI) U26.8(GND) U27.5(EI) U27.8(GND)
DVDD: C124.1 C125.1 R223.1 R224.1 R225.1 R226.1 R227.1 R228.1 R229.1 R230.1 R231.1 R232.1 R233.1 R234.1 R235.1 R236.1 R237.1 R238.1 U26.16(VCC) U27.16(VCC)
C2000_CLK: R292.1 ; port C2000_CLK
C2000_RESET2: C126.1 J5.120 S6.1
CS1: R280.1 ; port CS1
CS2: R285.2 ; port CS2
DACA: R221.1 ; port DACA
DIN1: R277.1 ; port DIN1
DIN2: R284.1 ; port DIN2
DIR: R58.1 ; port DIR
DOUT1: R279.1 ; port DOUT1
DOUT2: R286.1 ; port DOUT2
DRDY1: R278.1 ; port DRDY1
DRDY2: R283.1 ; port DRDY2
EN_A: R293.2 U26.9(A0)
EN_B: R294.2 U26.7(A1)
EN_C: R295.2 U26.6(A2)
EN_CH1: R226.2 S4.4 U26.10(0)
EN_CH2: R225.2 S4.3 U26.11(1)
EN_CH3: R224.2 S4.2 U26.12(2)
EN_CH4: R223.2 S4.1 U26.13(3)
EN_CH5: R227.2 S4.5 U26.1(4)
EN_CH6: R228.2 S4.6 U26.2(5)
EN_CH7: R229.2 S4.7 U26.3(6)
EN_CH8: R230.2 S4.8 U26.4(7)
EPWM_A1: R261.1 ; off-sheet EPWM_A1
EPWM_A2: R265.1 ; off-sheet EPWM_A2
EPWM_A3: R262.1 ; off-sheet EPWM_A3
EPWM_A4: R266.1 ; off-sheet EPWM_A4
EPWM_A5: R270.2 ; off-sheet EPWM_A5
EPWM_A6: R272.2 ; off-sheet EPWM_A6
EPWM_A7: R269.1 ; off-sheet EPWM_A7
EPWM_A8: R273.1 ; off-sheet EPWM_A8
EPWM_B1: R263.1 ; off-sheet EPWM_B1
EPWM_B2: R267.1 ; off-sheet EPWM_B2
EPWM_B3: R264.1 ; off-sheet EPWM_B3
EPWM_B4: R268.1 ; off-sheet EPWM_B4
EPWM_B5: R281.1 ; off-sheet EPWM_B5
EPWM_B6: R276.2 ; off-sheet EPWM_B6
EPWM_B7: R271.1 ; off-sheet EPWM_B7
EPWM_B8: R275.1 ; off-sheet EPWM_B8
FAULT: R289.1 ; port FAULT
Interrupt1: R167.1
Interrupt2: R166.1
Interrupt3: R165.1
Interrupt4: R164.1
Interrupt5: R171.1
Interrupt6: R170.1
Interrupt7: R169.1
Interrupt8: R168.1
IoutP1: R245.1 ; off-sheet IoutP1
IoutP2: R246.1 ; off-sheet IoutP2
IoutP3: R249.1 ; off-sheet IoutP3
IoutP4: R250.1 ; off-sheet IoutP4
IoutP5: R253.1 ; off-sheet IoutP5
IoutP6: R254.1 ; off-sheet IoutP6
IoutP7: R257.1 ; off-sheet IoutP7
IoutP8: R258.1 ; off-sheet IoutP8
MODE_A: R297.1 U27.9(A0)
MODE_B: R296.1 U27.7(A1)
MODE_C: R274.1 U27.6(A2)
MODE_CH1: R234.2 S5.4 U27.10(0)
MODE_CH2: R233.2 S5.3 U27.11(1)
MODE_CH3: R232.2 S5.2 U27.12(2)
MODE_CH4: R231.2 S5.1 U27.13(3)
MODE_CH5: R235.2 S5.5 U27.1(4)
MODE_CH6: R236.2 S5.6 U27.2(5)
MODE_CH7: R237.2 S5.7 U27.3(6)
MODE_CH8: R238.2 S5.8 U27.4(7)
RESET1: R282.1 ; port RESET1
SCLK1: R298.1 ; port SCLK1
SCLK2: R288.1 ; port SCLK2
VoutP1: R247.1 ; off-sheet VoutP1
VoutP2: R248.1 ; off-sheet VoutP2
VoutP3: R251.1 ; off-sheet VoutP3
VoutP4: R252.1 ; off-sheet VoutP4
VoutP5: R255.1 ; off-sheet VoutP5
VoutP6: R256.1 ; off-sheet VoutP6
VoutP7: R259.1 ; off-sheet VoutP7
VoutP8: R260.1 ; off-sheet VoutP8
NetD33_2: D33.2(A) R59.2
NetJ5_9: J5.9 R221.2 R245.2
NetJ5_11: J5.11 R246.2
NetJ5_12: J5.12 R247.2
NetJ5_14: J5.14 R248.2
NetJ5_15: J5.15 R249.2
NetJ5_17: J5.17 R250.2
NetJ5_18: J5.18 R251.2
NetJ5_20: J5.20 R252.2
NetJ5_31: J5.31 R253.2
NetJ5_33: J5.33 R254.2
NetJ5_34: J5.34 R255.2
NetJ5_36: J5.36 R256.2
NetJ5_37: J5.37 R257.2
NetJ5_39: J5.39 R258.2
NetJ5_40: J5.40 R259.2
NetJ5_42: J5.42 R260.2
NetJ5_49: J5.49 R261.2
NetJ5_50: J5.50 R262.2
NetJ5_51: J5.51 R263.2
NetJ5_52: J5.52 R264.2
NetJ5_53: J5.53 R265.2
NetJ5_54: J5.54 R266.2
NetJ5_55: J5.55 R267.2
NetJ5_56: J5.56 R268.2
NetJ5_57: J5.57 R269.2
NetJ5_58: J5.58 R293.1
NetJ5_59: J5.59 R271.2
NetJ5_60: J5.60 R294.1
NetJ5_61: J5.61 R273.2
NetJ5_62: J5.62 R295.1
NetJ5_63: J5.63 R275.2
NetJ5_64: J5.64 R274.2
NetJ5_67: J5.67 R277.2
NetJ5_68: J5.68 R278.2
NetJ5_69: J5.69 R279.2
NetJ5_70: J5.70 R280.2
NetJ5_71: J5.71 R281.2
NetJ5_72: J5.72 R282.2
NetJ5_73: J5.73 R276.1
NetJ5_74: J5.74 R283.2
NetJ5_75: J5.75 R284.2
NetJ5_77: J5.77 R286.2
NetJ5_79: J5.79 R288.2
NetJ5_80: J5.80 R289.2
NetJ5_81: J5.81 R285.1
NetJ5_82: J5.82 R59.1
NetJ5_85: J5.85 R272.1
NetJ5_86: J5.86 R58.2
NetJ5_87: J5.87 R270.1
NetJ5_99: J5.99 R292.2
NetJ5_101: J5.101 R297.2
NetJ5_103: J5.103 R298.2
NetJ5_105: J5.105 R296.2
NetJ6_121: J6.121 R164.2
NetJ6_123: J6.123 R165.2
NetJ6_125: J6.125 R166.2
NetJ6_127: J6.127 R167.2
NetJ6_129: J6.129 R168.2
NetJ6_131: J6.131 R169.2
NetJ6_133: J6.133 R170.2
NetJ6_137: J6.137 R171.2

Not connected (* = marked no-connect by the designer): J5 1 2 3 4 5 6 8 21 23 24 25 26 27 28 30 32 41 43 44 45 66* 76 78 88 89 90 91 92 93 94 95 96 100 102 104 106 107 108 109 110 113 114 115 116 117 118 119; J6 122 124 126 128 130 132 134 136 138 139 140 141 142 143 144 145 146 147 148 149 150 151 152 153 154 155 156 159 160 161 162 163 164 165 166 167 168 169 170 171 172 173 174 175 176 177 178; U26 14(GS)* 15(EO)*; U27 14(GS)* 15(EO)*

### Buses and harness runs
bus EPWM_A[1..8] = port EPWM_A[1..8]
bus EPWM_B[1..8] = port EPWM_B[1..8]
bus Interrupt[1..8] = port Interrupt[1..8]
bus IoutP[1..8] = port IoutP[1..8]
bus VoutP[1..8] = port VoutP[1..8]

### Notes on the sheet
- CONTROL CARD PIN MAPPING_28379

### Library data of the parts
C124 C125 = CMP-0007405-4: CAP, CERM, 1 uF, 25 V, +/- 10%, X7R, 0603; PartNumber: GRM188R71E105KA12D; Manufacturer: MuRata; Polarized: N; Value: 1uF; U/M: EA; Cap_F: 1µF; Value1: Unknown; VDC_V: 25V; TaMin_C: -55°C; TaMax_C: 125°C; AEC Category: Q200; SizeArea_mm2: 1.28; SizeAreaWB_mm2: 4.68; SizeX_mm: 1.6; SizeY_mm: 0.8; SizeZ_mm: 1
C126 = C0603C103J3GECAUTO: CAP, CERM, 0.01 µF, 25 V,+/- 5%, C0G/NP0, AEC-Q200 Grade 1, 0603; Manufacturer: Kemet; Polarized: N; CompType: Capacitor; Value: 0.01uF; U/M: EA; Cap_F: 0.00000001; Tolerance_%: 5; VDC_V: 25; Value2: 25V; TaMin_C: -55; TaMax_C: 125; SizeArea_mm2: 1.28; SizeAreaWB_mm2: 4.68; SizeX_mm: 1.6; SizeY_mm: 0.8; SizeZ_mm: 1; AEC Category: Q200; AEC Qualified: Y
D33 = 150060VS75000: as D11 on sheet XTIDA-010086_Bias Power Supply
J5 = CMP-0003814-2: C2000 controlCARD-120HSEC connector, SMT; Manufacturer: Samtec; Note: The pin numbering does not match Samtec datasheet
J6 = CMP-0003859-2: C2000 controlCARD-180HSEC (60-pin addon) connector, SMT; Manufacturer: Samtec; Note: The pin numbering does not match Samtec datasheet
R58 R164-R171 R221 R245-R276 R278 R281 R283 R289 R293-R297 = CRCW04020000Z0ED: as R188 on sheet XTIDA-010086_Bias Power Supply
R59 = CRCW06034K99FKEA: as R178 on sheet XTIDA-010086_Bias Power Supply
R223-R238 = CRCW040210K0FKED: RES, 10.0 k, 1%, 0.063 W, 0402; Manufacturer: Vishay-Dale; CompType: Resistor; Value: 10.0k; Res_ohm: 10000; Value_Code: 10k0; Tolerance_%: 1; Power_W: 0.063; Value2: 0.063W; VDC_V: 50; TempCo: 100 ppm/C; SizeArea_mm2: 0.5; SizeZ_mm: 0.6; EIA_Code: E96; U/M: EA; AEC Category: Q200; Green_Lifecycle: Active; Green_REACh: Passed
R277 R279 R280 R282 R284-R286 R288 R292 R298 = FC0402E50R0BST1: RES, 50, 0.1%, 0.05 W, 0402; Manufacturer: Vishay-Dale; CompType: Resistor; Value: 50; Value_Code: 50R0; Tolerance_%: 0.1; Power_W: 0.05; Value2: 0.05W; TempCo: 25 ppm/C; SizeArea_mm2: 0.5; SizeX_mm: 1; SizeZ_mm: 0.6; U/M: EA; AEC Category: Q200; AEC Qualified: N
S4 S5 = CMP-0002229-1: Switch, SPST, 8 Pos, 25mA, 24VDC, SMD; Manufacturer: CTS Electrocomponents; CurrentRating_mA: 25A; PositionCount: 8; VDC_V: 24V; SwitchFunction: Off-On
S6 = CMP-0002143-3: Switch, Tactile, SPST-NO, 0.05A, 12V, SMT; PartNumber: TL1015AF160QG; Manufacturer: E-Switch; SwitchFunction: Off-Mom; PositionCount: 1; CurrentRating_mA: 50A
TP41 = 5001: as TP34-TP36 on sheet XTIDA-010086_Bias Power Supply
U26 U27 = CMP-0088185-1: Priority Encoder 1 x 8:3 16-SOIC; Manufacturer: Texas Instruments; SizeZ_mm: 1.75mm; AEC Qualified: No

## Sheet XTIDA-010086_CoverSheet.SchDoc: Block diagram
size 431 x 279 mm; Date: Not shown in title block; ApprovedBy: Not shown in title block; CheckedBy: Not shown in title block; Author: Not shown in title block; CompanyName: Not shown in title block; DrawnBy: Jeff Xie; Engineer: Not shown in title block; Organization: Not shown in title block; Address1: Not shown in title block; Address2: Not shown in title block; Address3: Not shown in title block; Address4: Not shown in title block; DocumentNumber: 1; Revision: Use project parameter SCH_Rev; SheetNumber: 1; SheetTotal: 8; PageSetup: Record=PageOptions¦CenterHorizontal=True¦CenterVertical=True¦PrintScale=1.00¦XCorrection=1.00¦YCorrection=1.00¦PrintKind=0¦BorderSize=5000000¦LeftOffset=0¦BottomOffset=0¦Orientation=2¦PaperLength=1000¦PaperWidth=1000¦Scale=100¦PaperSource=15¦PrintQuality=600¦MediaType=1¦DitherType=10¦PaperKind=Letter¦PrintScaleMode=1
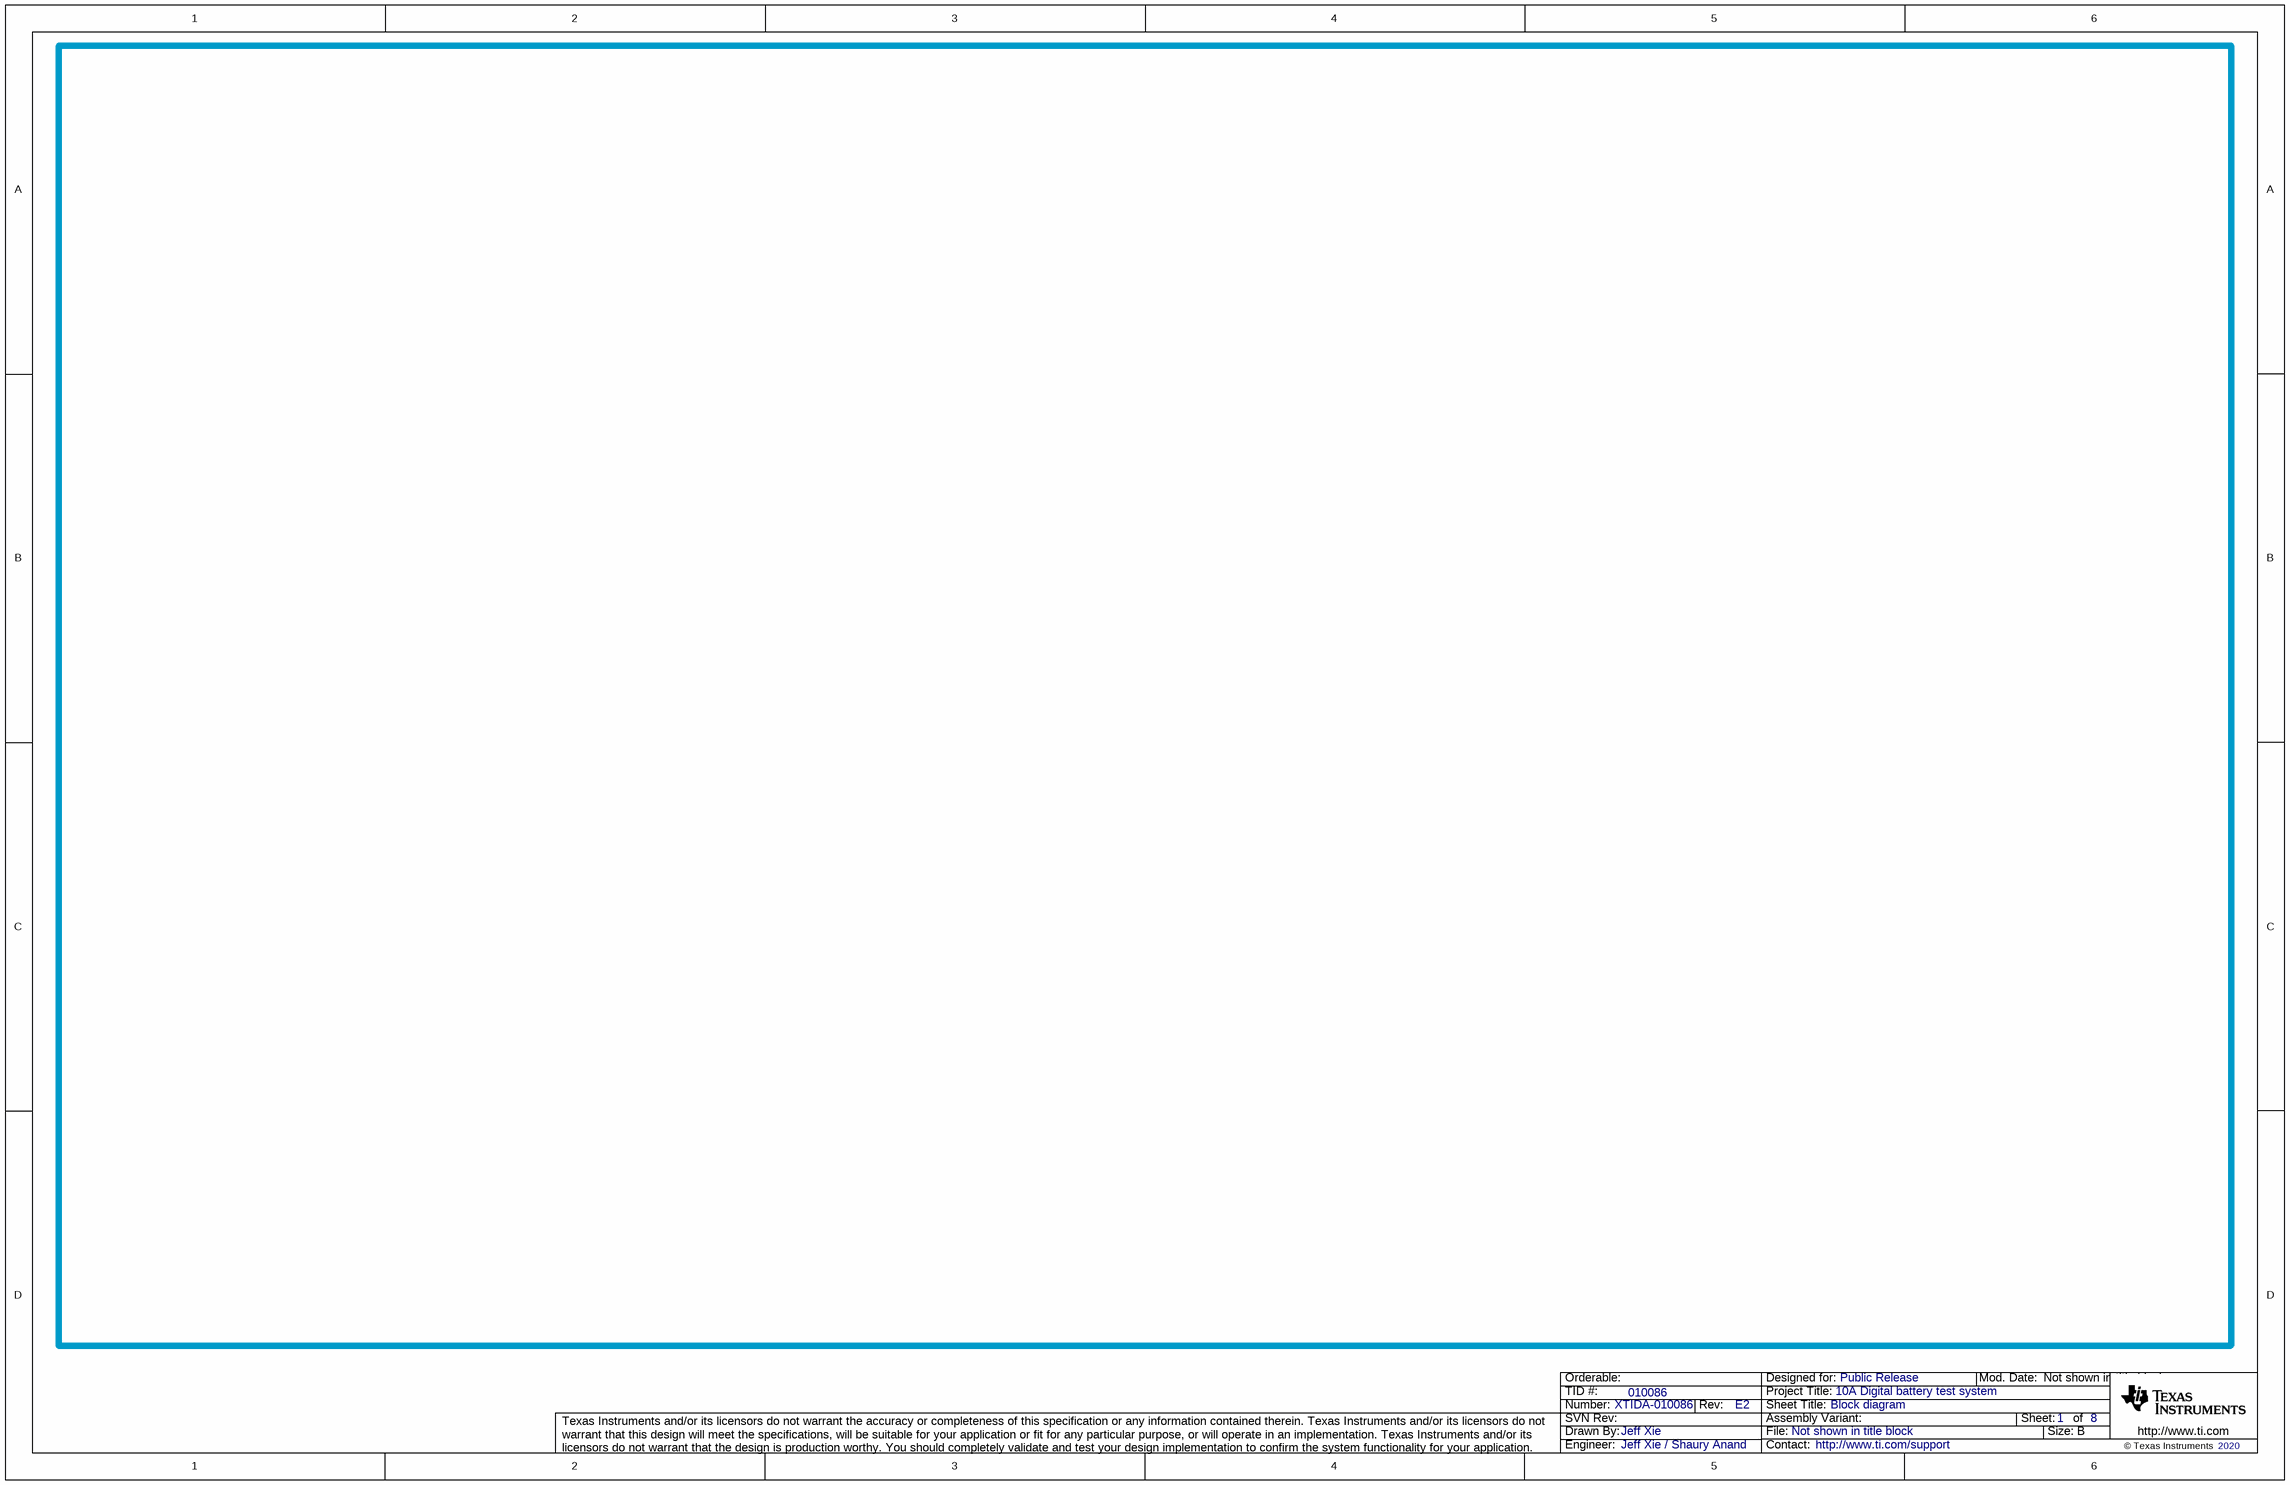
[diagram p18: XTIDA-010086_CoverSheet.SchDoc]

## Sheet XTIDA-010086_Hardware.SchDoc
size 431 x 279 mm; Date: Not shown in title block; ApprovedBy: Not shown in title block; CheckedBy: Not shown in title block; Author: Not shown in title block; CompanyName: Not shown in title block; Engineer: Not shown in title block; Organization: Not shown in title block; Address1: Not shown in title block; Address2: Not shown in title block; Address3: Not shown in title block; Address4: Not shown in title block; DocumentNumber: 3; Revision: Use project parameter SCH_Rev; SheetNumber: 8; SheetTotal: 8; PageSetup: Record=PageOptions¦CenterHorizontal=True¦CenterVertical=True¦PrintScale=1.00¦XCorrection=1.00¦YCorrection=1.00¦PrintKind=0¦BorderSize=5000000¦LeftOffset=0¦BottomOffset=0¦Orientation=2¦PaperLength=1000¦PaperWidth=1000¦Scale=100¦PaperSource=15¦PrintQuality=600¦MediaType=1¦DitherType=10¦PaperKind=Letter¦PrintScaleMode=1
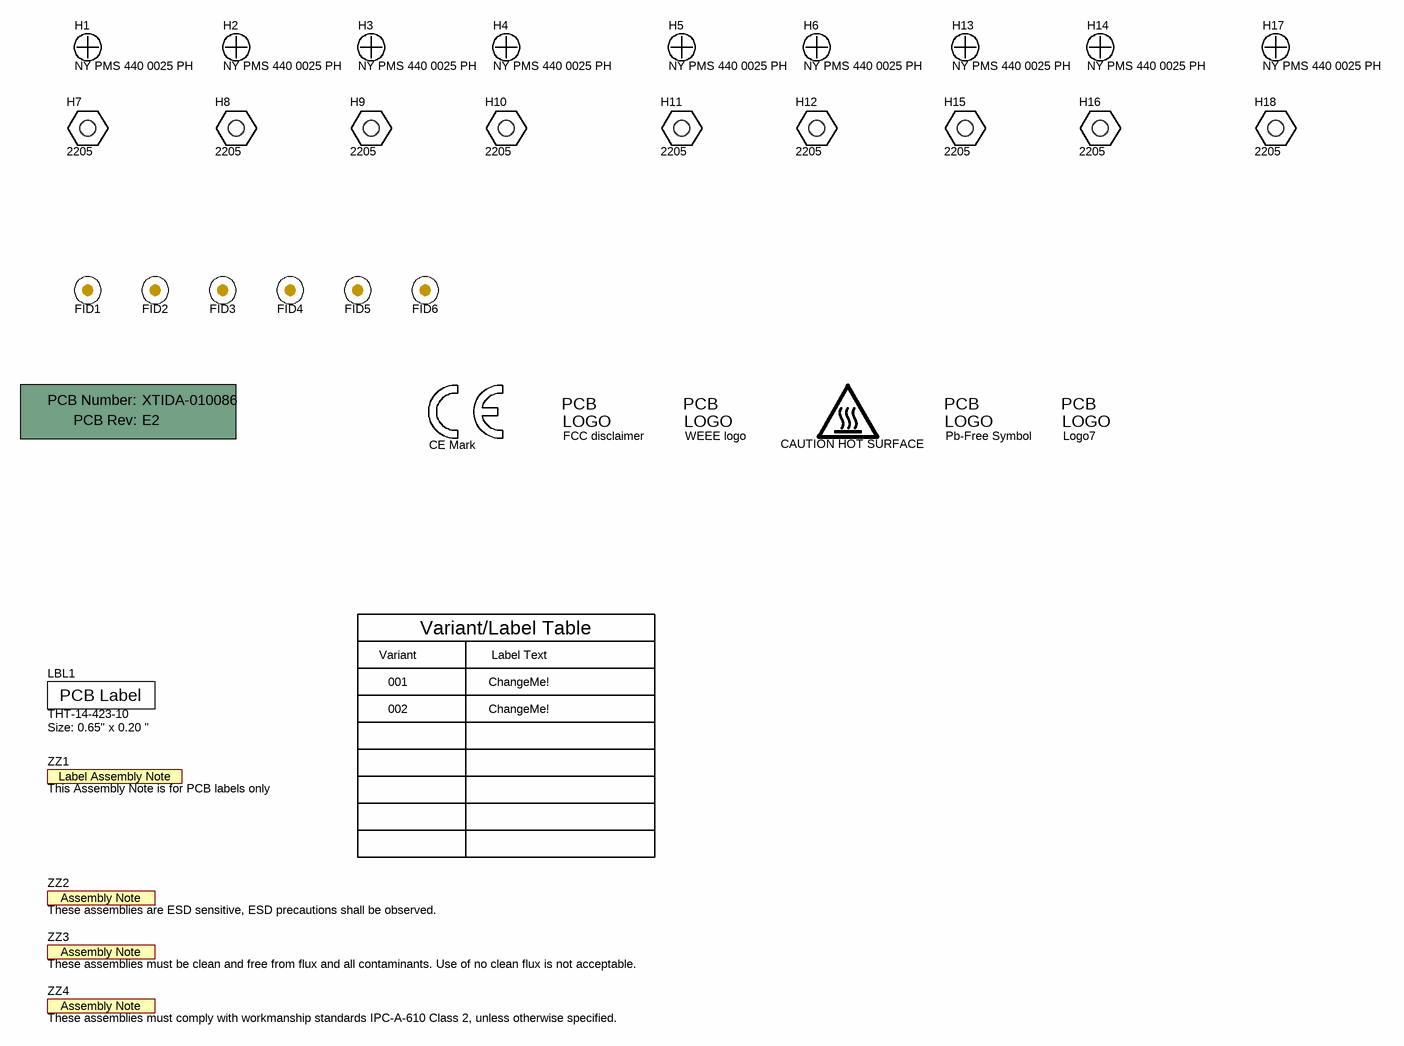
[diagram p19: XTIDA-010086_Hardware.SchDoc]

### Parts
!PCB1  Printed Circuit Board  (value not drawn)  (mechanical)
FID1  Fiducial  [Fiducial10-20]  (value not drawn)
FID2  Fiducial  [Fiducial10-20]  (value not drawn)
FID3  Fiducial  [Fiducial10-20]  (value not drawn)
FID4  Fiducial  [Fiducial10-20]  (value not drawn)
FID5  Fiducial  [Fiducial10-20]  (value not drawn)
FID6  Fiducial  [Fiducial10-20]  (value not drawn)
H1  NY PMS 440 0025 PH  [NY PMS 440 0025 PH]
H2  NY PMS 440 0025 PH  [NY PMS 440 0025 PH]
H3  NY PMS 440 0025 PH  [NY PMS 440 0025 PH]
H4  NY PMS 440 0025 PH  [NY PMS 440 0025 PH]
H5  NY PMS 440 0025 PH  [NY PMS 440 0025 PH]
H6  NY PMS 440 0025 PH  [NY PMS 440 0025 PH]
H7  2205  [KEYSTONE_2205]
H8  2205  [KEYSTONE_2205]
H9  2205  [KEYSTONE_2205]
H10  2205  [KEYSTONE_2205]
H11  2205  [KEYSTONE_2205]
H12  2205  [KEYSTONE_2205]
H13  NY PMS 440 0025 PH  [NY PMS 440 0025 PH]
H14  NY PMS 440 0025 PH  [NY PMS 440 0025 PH]
H15  2205  [KEYSTONE_2205]
H16  2205  [KEYSTONE_2205]
H17  NY PMS 440 0025 PH  [NY PMS 440 0025 PH]
H18  2205  [KEYSTONE_2205]
LBL1  THT-14-423-10  Note: Size: 0.65" x 0.20 "  [Label_650x200]
Logo1  CE Mark  [CE_Mark_5mm]  (no BOM)
Logo3  FCC disclaimer  [FCC_disclaimer]  (no BOM)
Logo4  WEEE logo  [WEEE_Minimum]  (no BOM)
LOGO5  CAUTION HOT SURFACE  [IEC_HotSurface_Small]  (no BOM)
Logo6  Pb-Free Symbol  [Pb-Free_Overlay_Small]  (no BOM)
Logo7  ESD Susceptible  [ESD_Overlay_Medium]  (value not drawn)  (no BOM)
ZZ1  This Assembly Note is for PCB labels only  [AssemblyNoteLabel]  (no BOM)
ZZ2  These assemblies are ESD sensitive, ESD precautions shall be observed.  [AssemblyNote]  (no BOM)
ZZ3  These assemblies must be clean and free from flux and all contaminants. Use of no clean flux is not acceptable.  [AssemblyNote]  (no BOM)
ZZ4  These assemblies must comply with workmanship standards IPC-A-610 Class 2, unless otherwise specified.  [AssemblyNote]  (no BOM)

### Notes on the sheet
- Variant
- Variant/Label Table
- Label Text
- 001
- 002
- ChangeMe!

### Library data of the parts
!PCB1 = CMP-0003618-2: Manufacturer: Any; PartNumber: XTIDA-010086
FID1-FID6 = Fiducial: Fiducial mark.  There is nothing to buy or mount.; SymbolCreator: codlsc
H1-H6 H13 H14 H17 = NY PMS 440 0025 PH: Machine Screw, Round, #4-40 x 1/4, Nylon, Philips panhead; Manufacturer: B&F Fastener Supply; CompType: Hardware; SymbolCreator: codlsc; U/M: EA
H7-H12 H15 H16 H18 = 2205: Standoff, Hex, 1"L #4-40 Aluminum; Manufacturer: Keystone; SymbolCreator: a0412235
LBL1 = CMP-0003625-1: Thermal Transfer Printable Labels, 0.650" W x 0.200" H - 10,000 per roll; Manufacturer: Brady; CompType: Label
Logo1 = CMP-0074844-1: SymbolCreator: a0412235
Logo3 = CMP-0074847-1: FCC_disclaimer; Library Reference: Logo
Logo4 = CMP-0074769-1
LOGO5 = CMP-0074837-1: IEC 61010-1 Hot Surface Warning; Library Reference: IEC_HotSurface; SymbolCreator: a0412235
Logo6 = Pb-Free: SymbolCreator: a0412235
Logo7 = ESD_Susceptible: ESD Susceptible Symbol; SymbolCreator: a0412235
ZZ1 = CMP-0003616-3
ZZ2 = CMP-0077236-1
ZZ3 = CMP-0077237-1
ZZ4 = CMP-0077238-1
